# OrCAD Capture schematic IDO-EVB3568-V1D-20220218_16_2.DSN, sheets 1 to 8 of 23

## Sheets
1 P01. Revision History: title: IDO-EVB3568-V1; note: Revision History
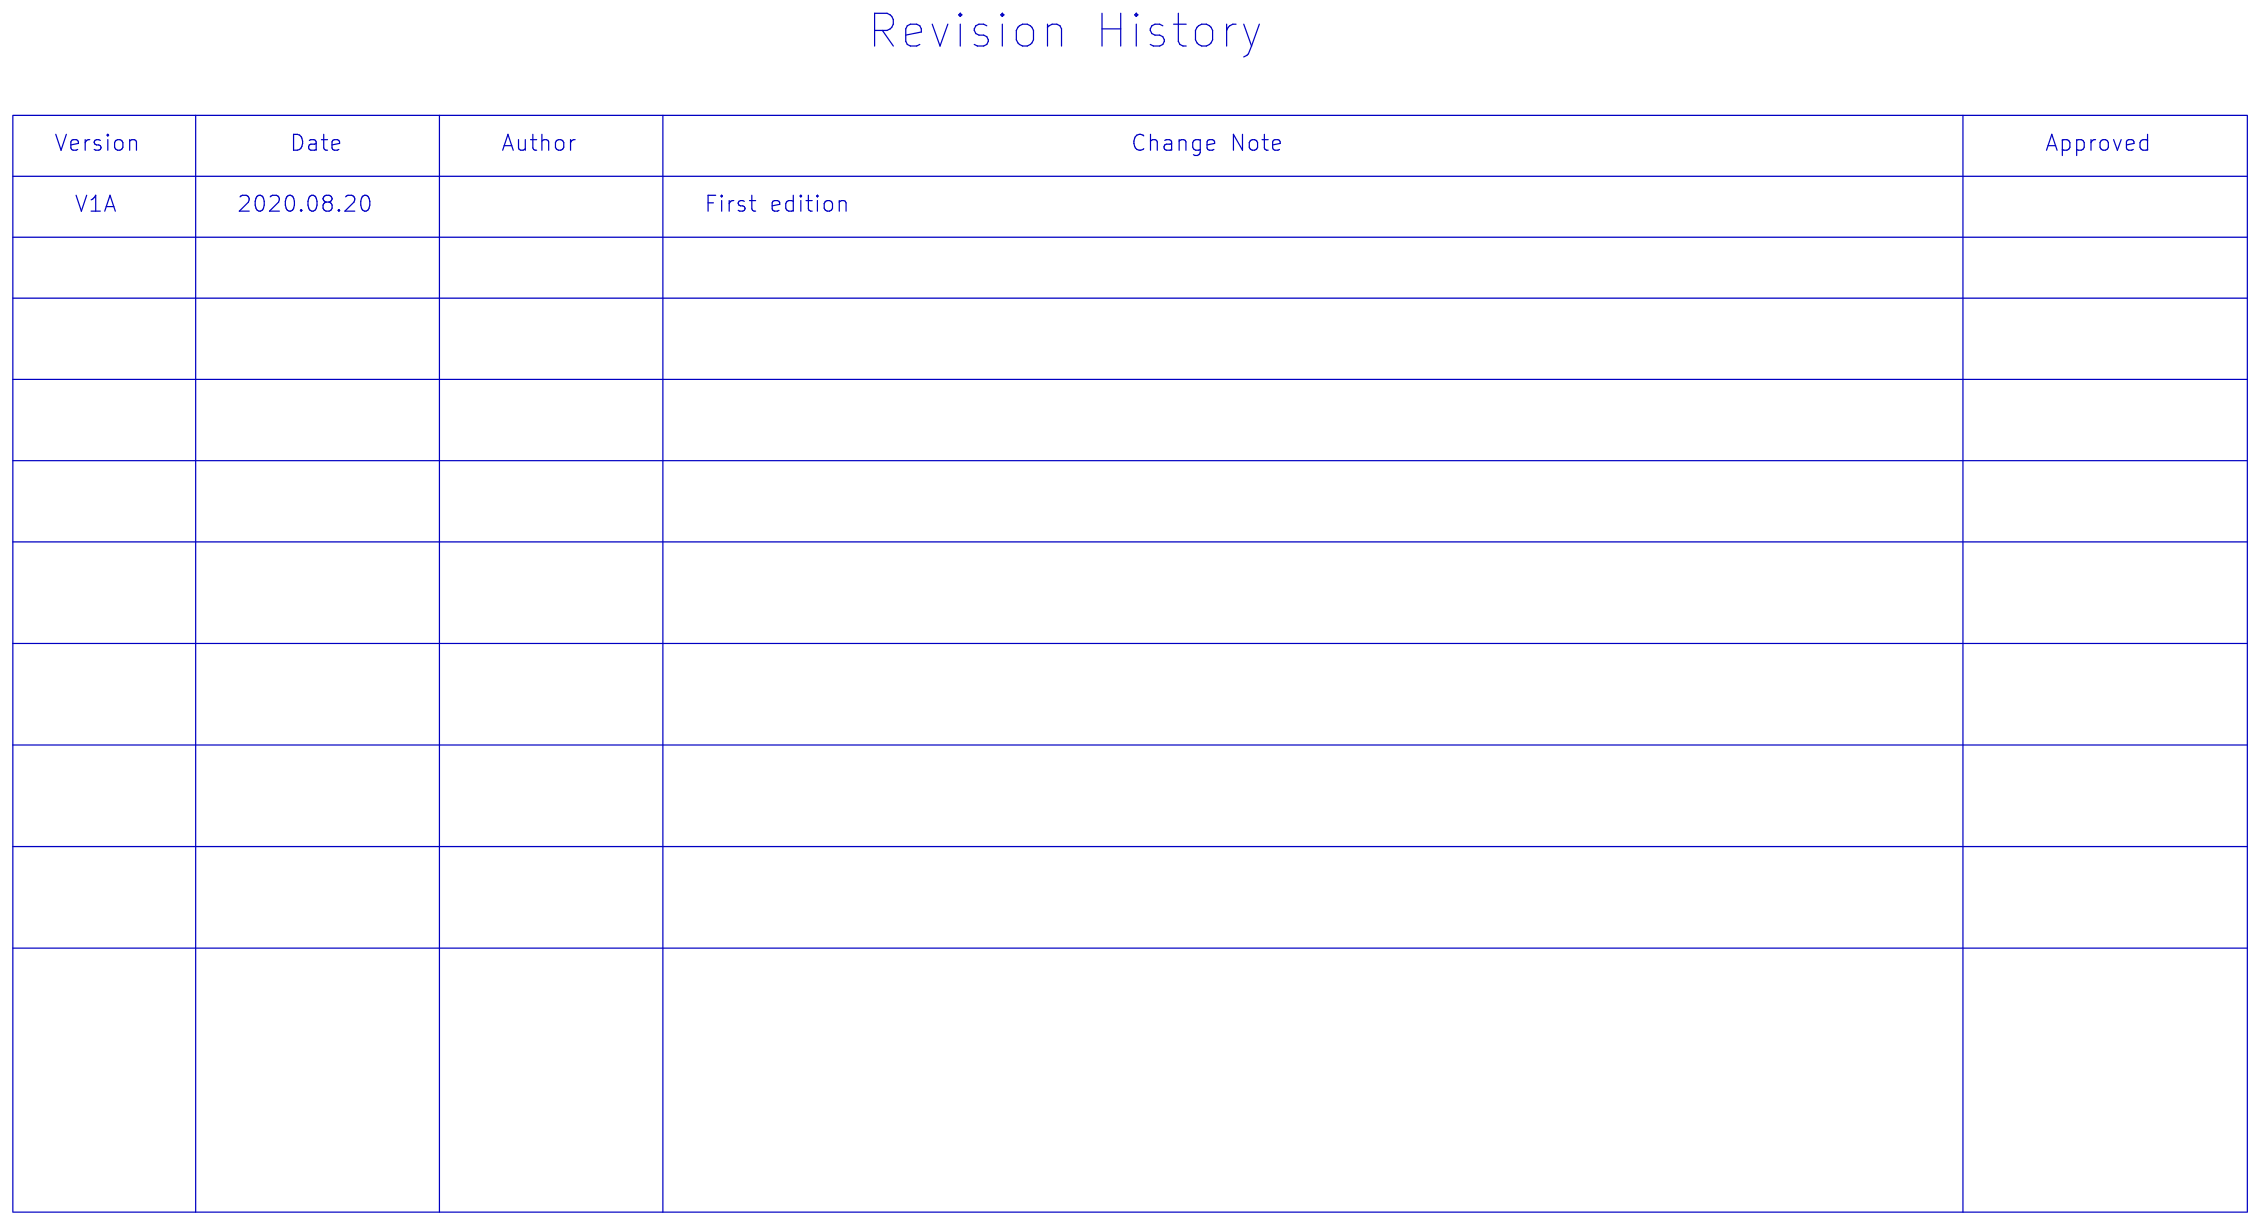
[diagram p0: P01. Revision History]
2 P02. Block Diagram: note: Block Diagram
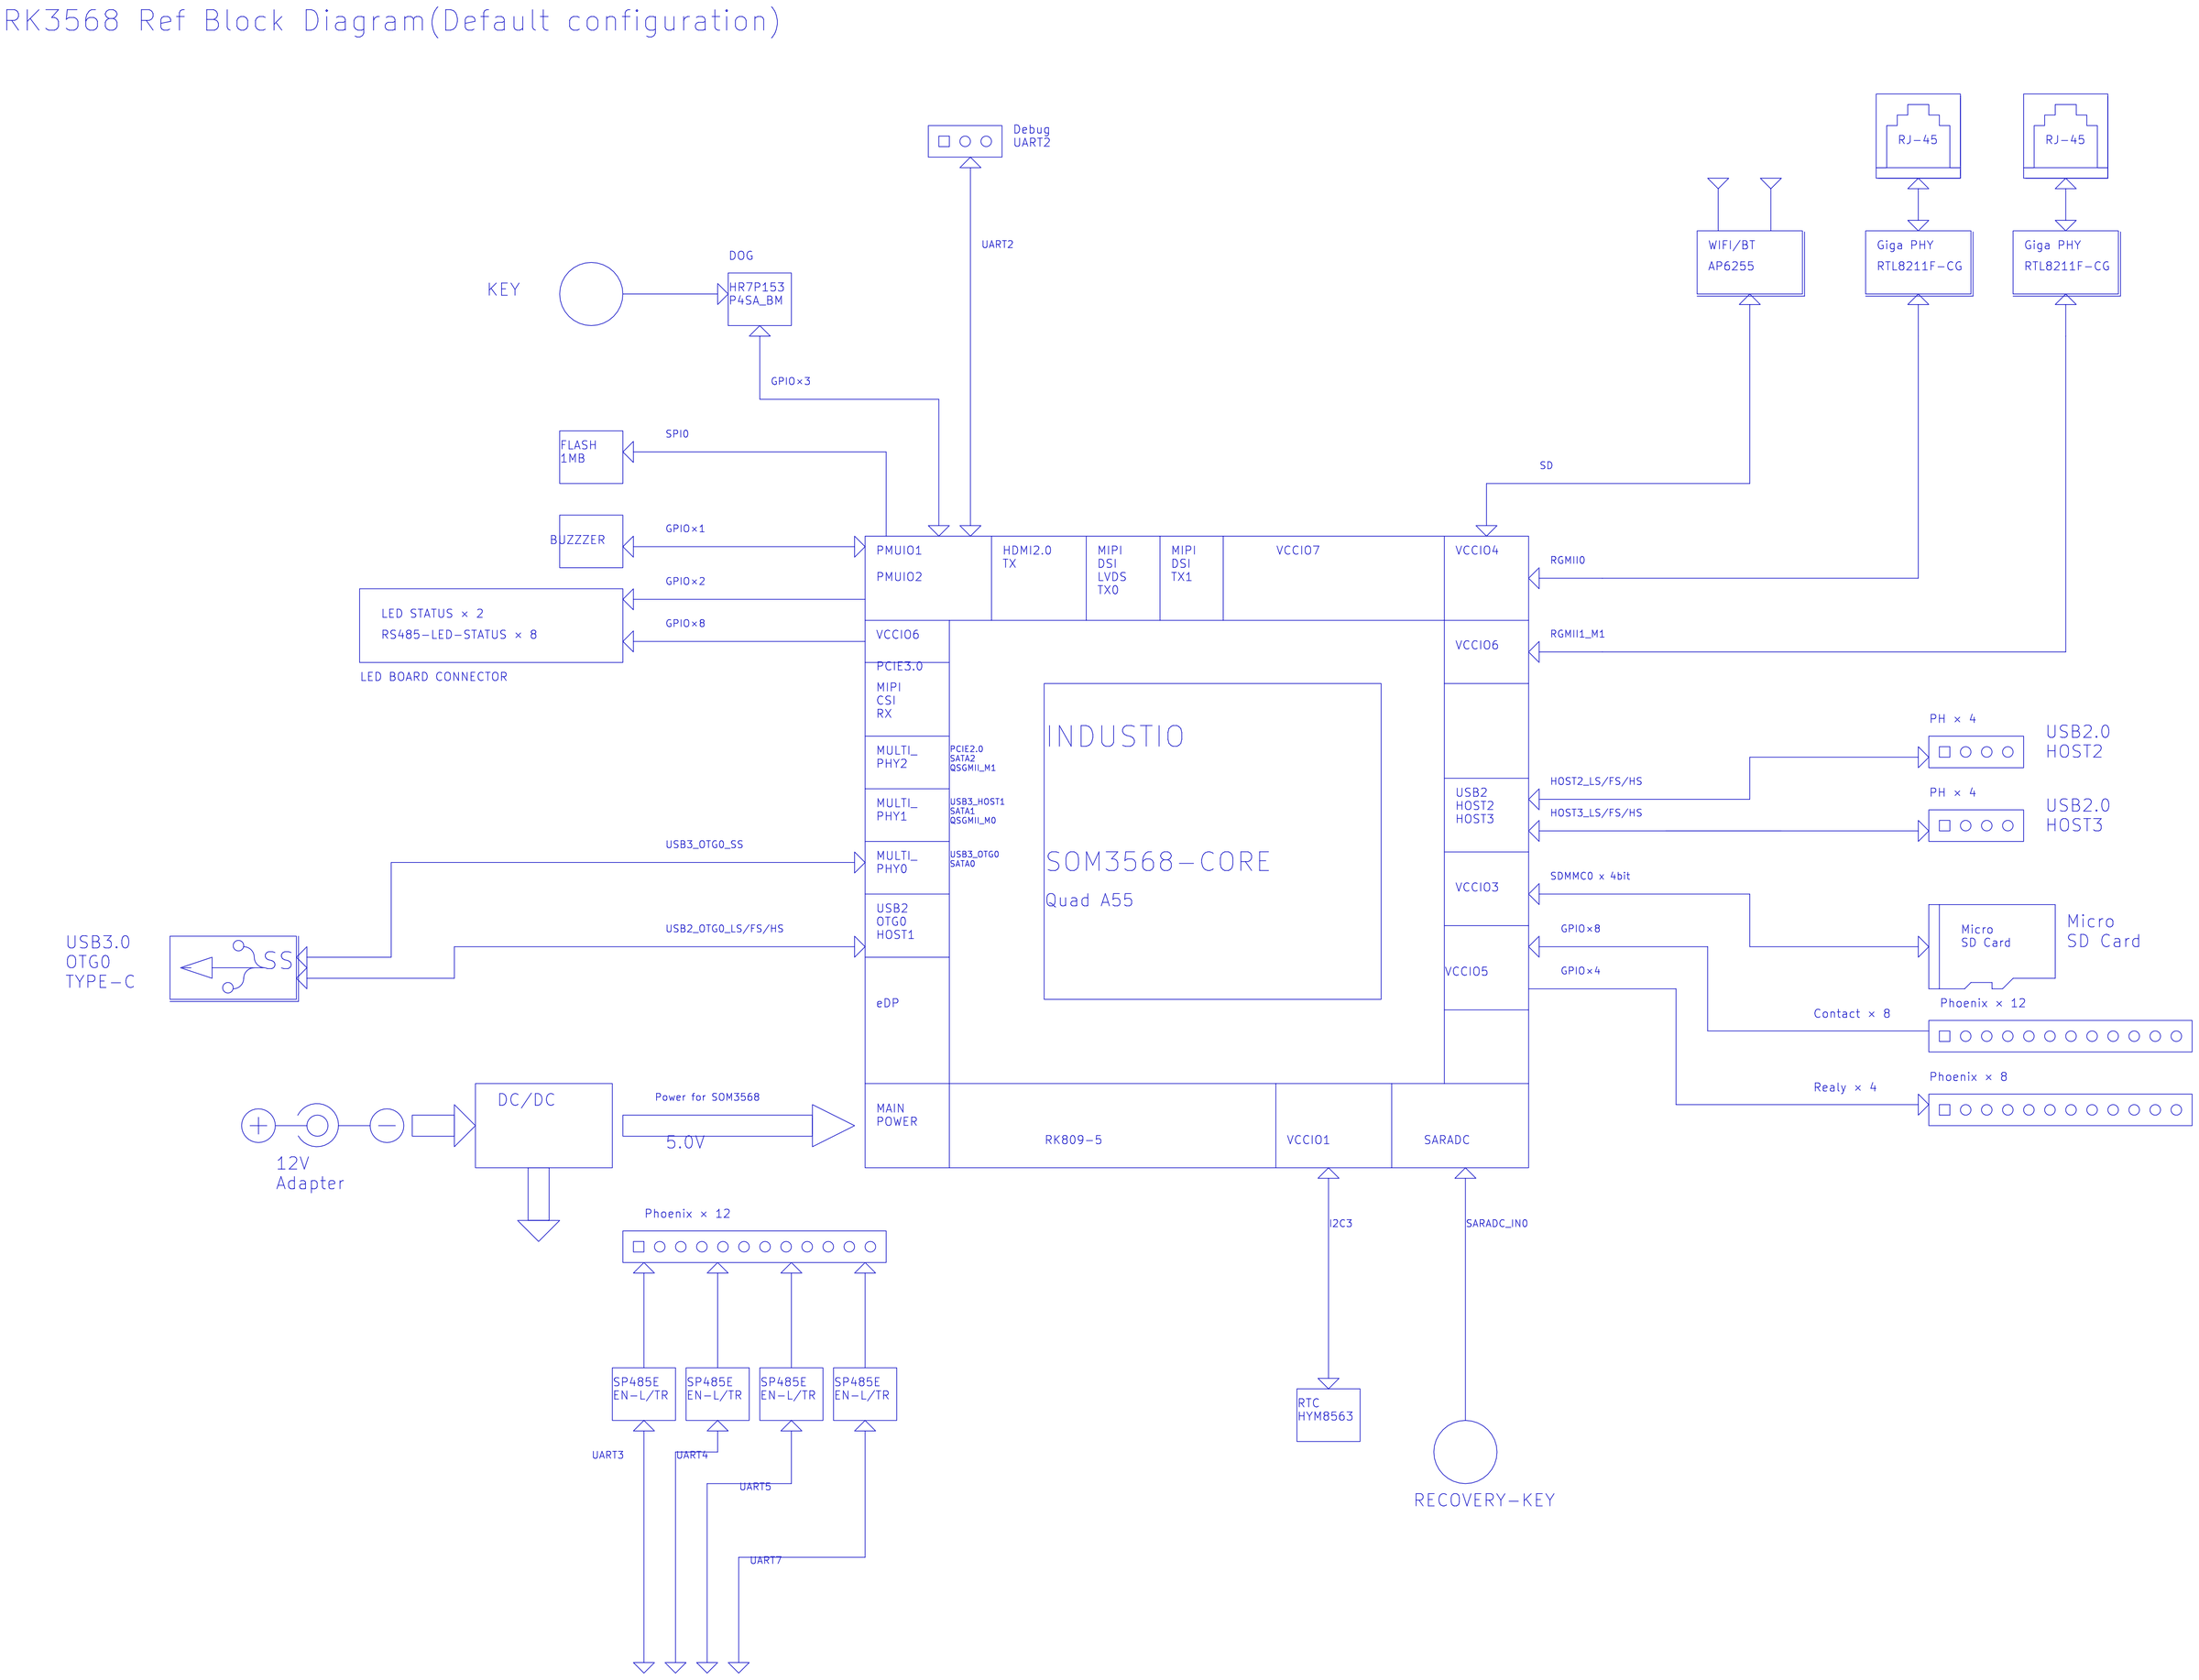
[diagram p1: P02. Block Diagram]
3 P03. Power Diagram: note: Power Diagram
4 P04. Power_DC IN: size A3; note: Power_DC IN
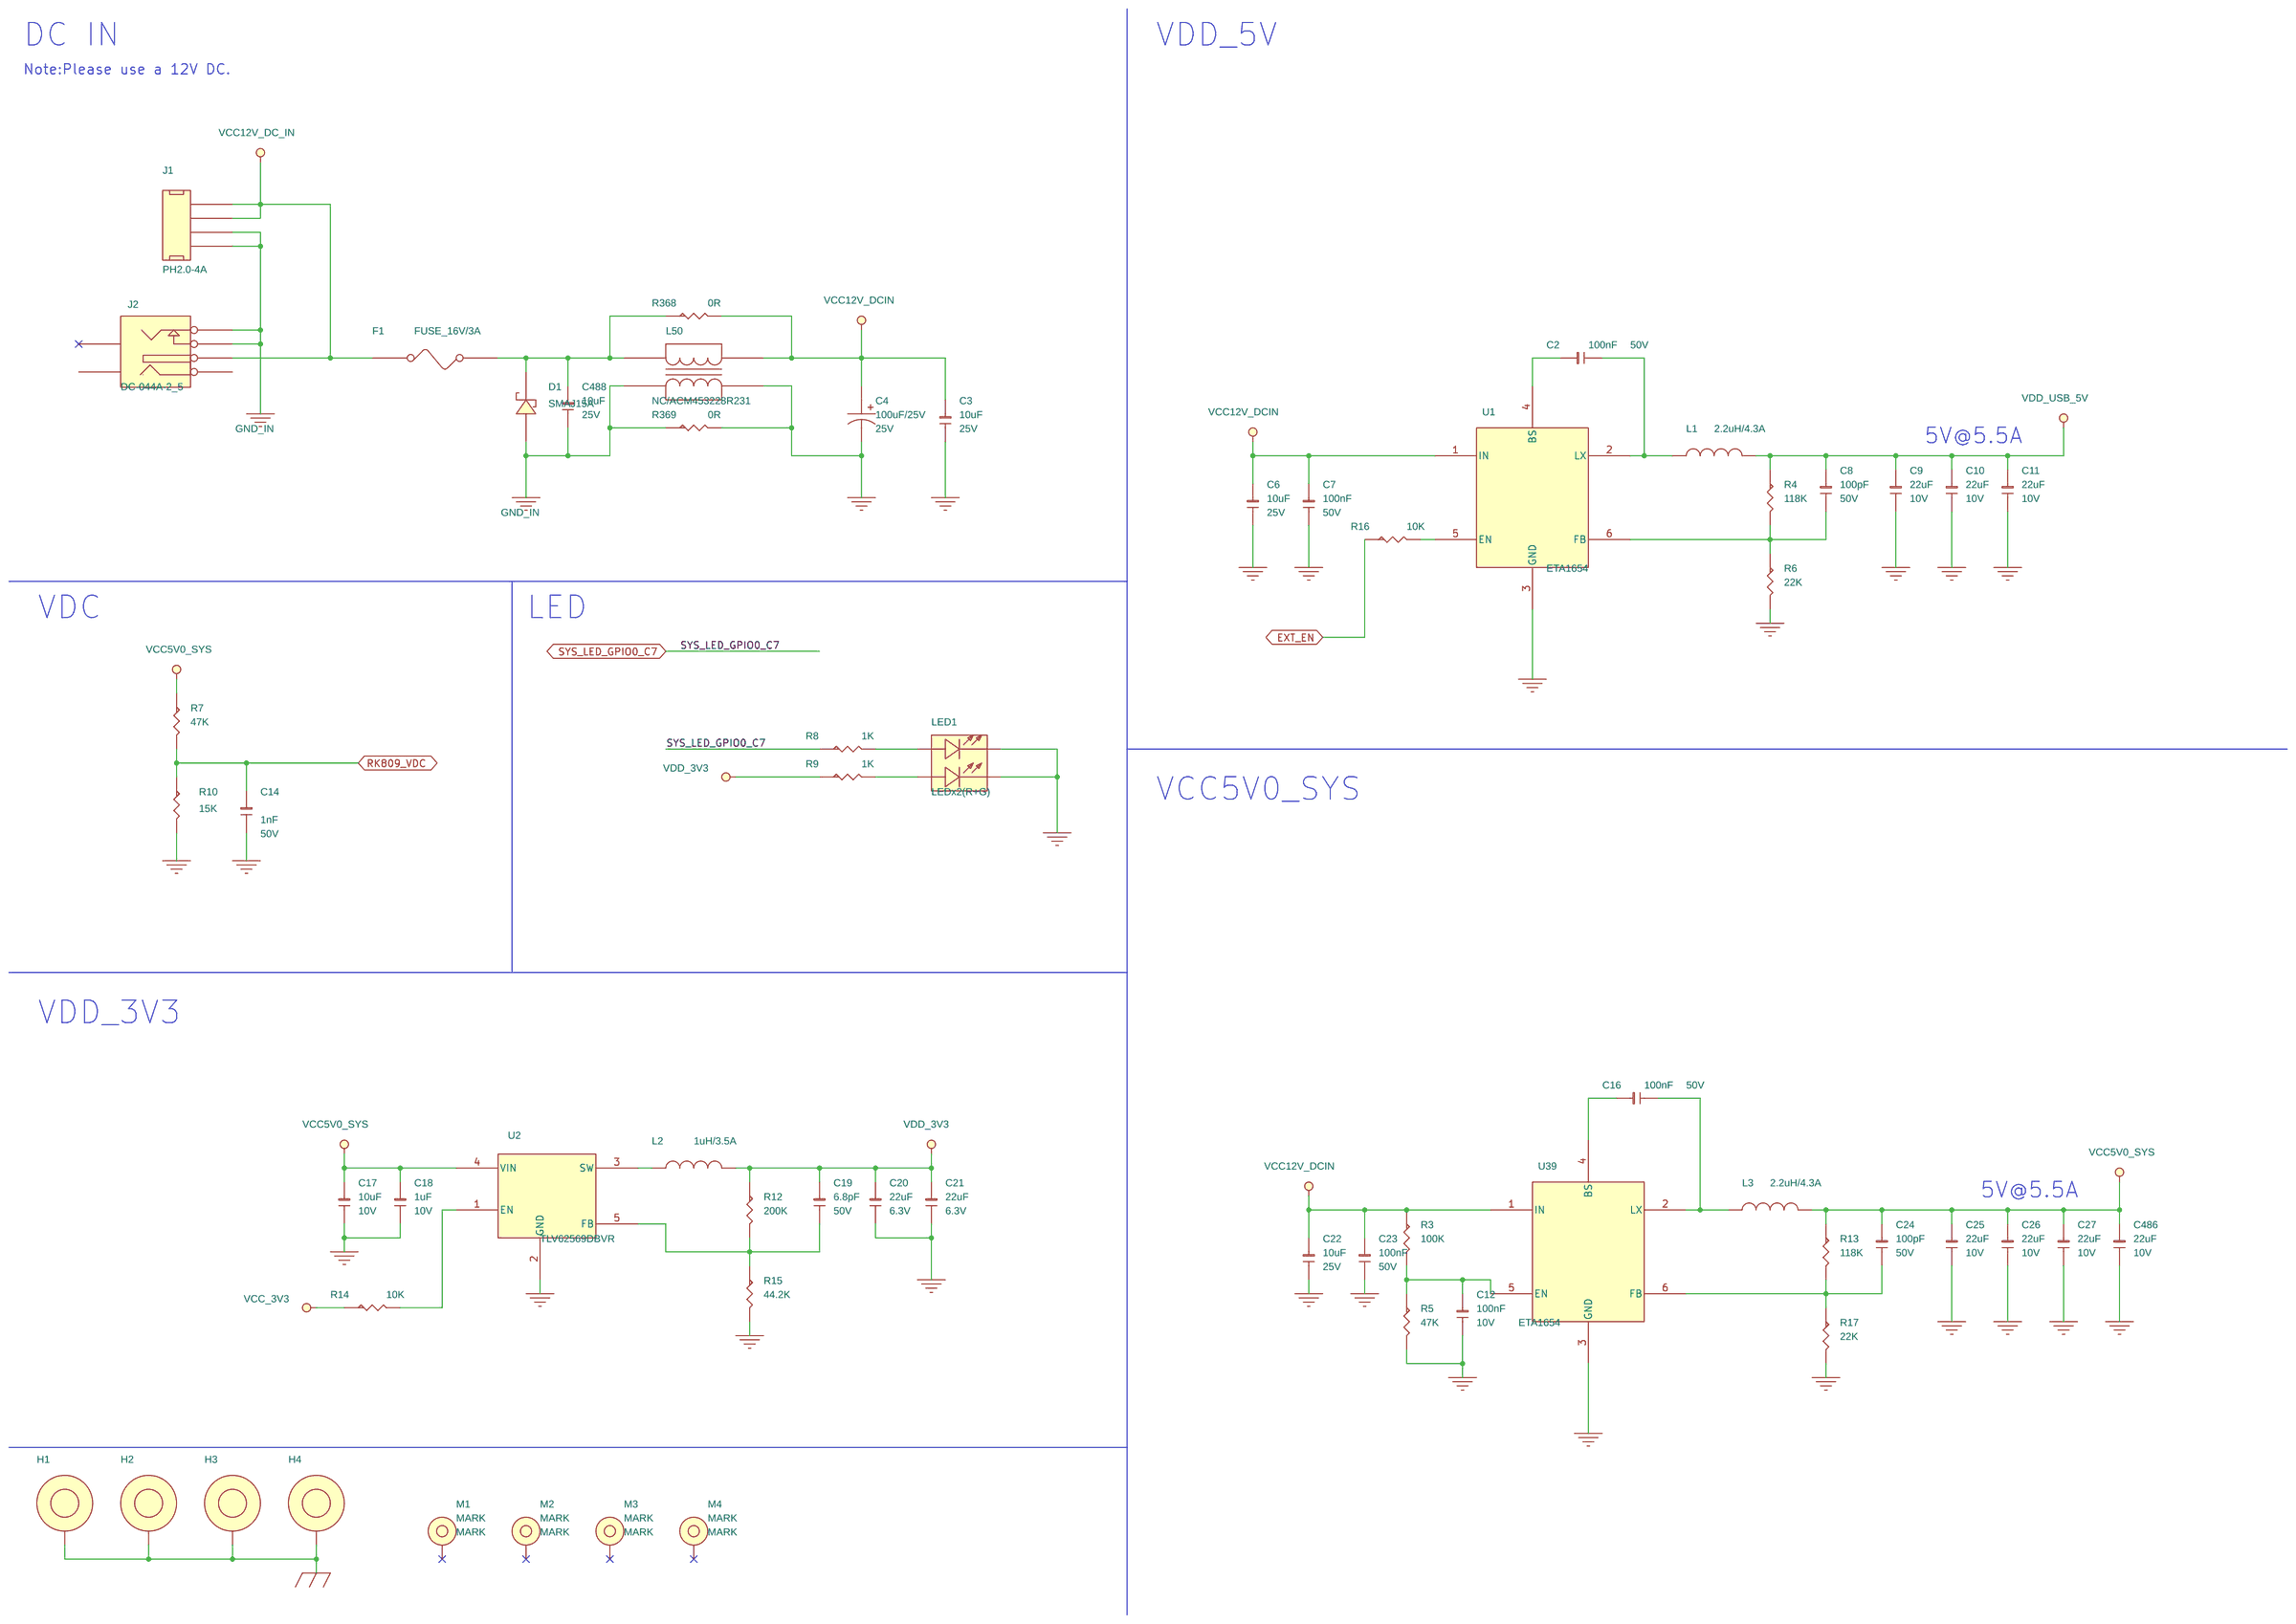
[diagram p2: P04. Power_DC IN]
5 P05. SOM3568-RK3568-Core: size A1; note: SOM3568-RK3568-Core
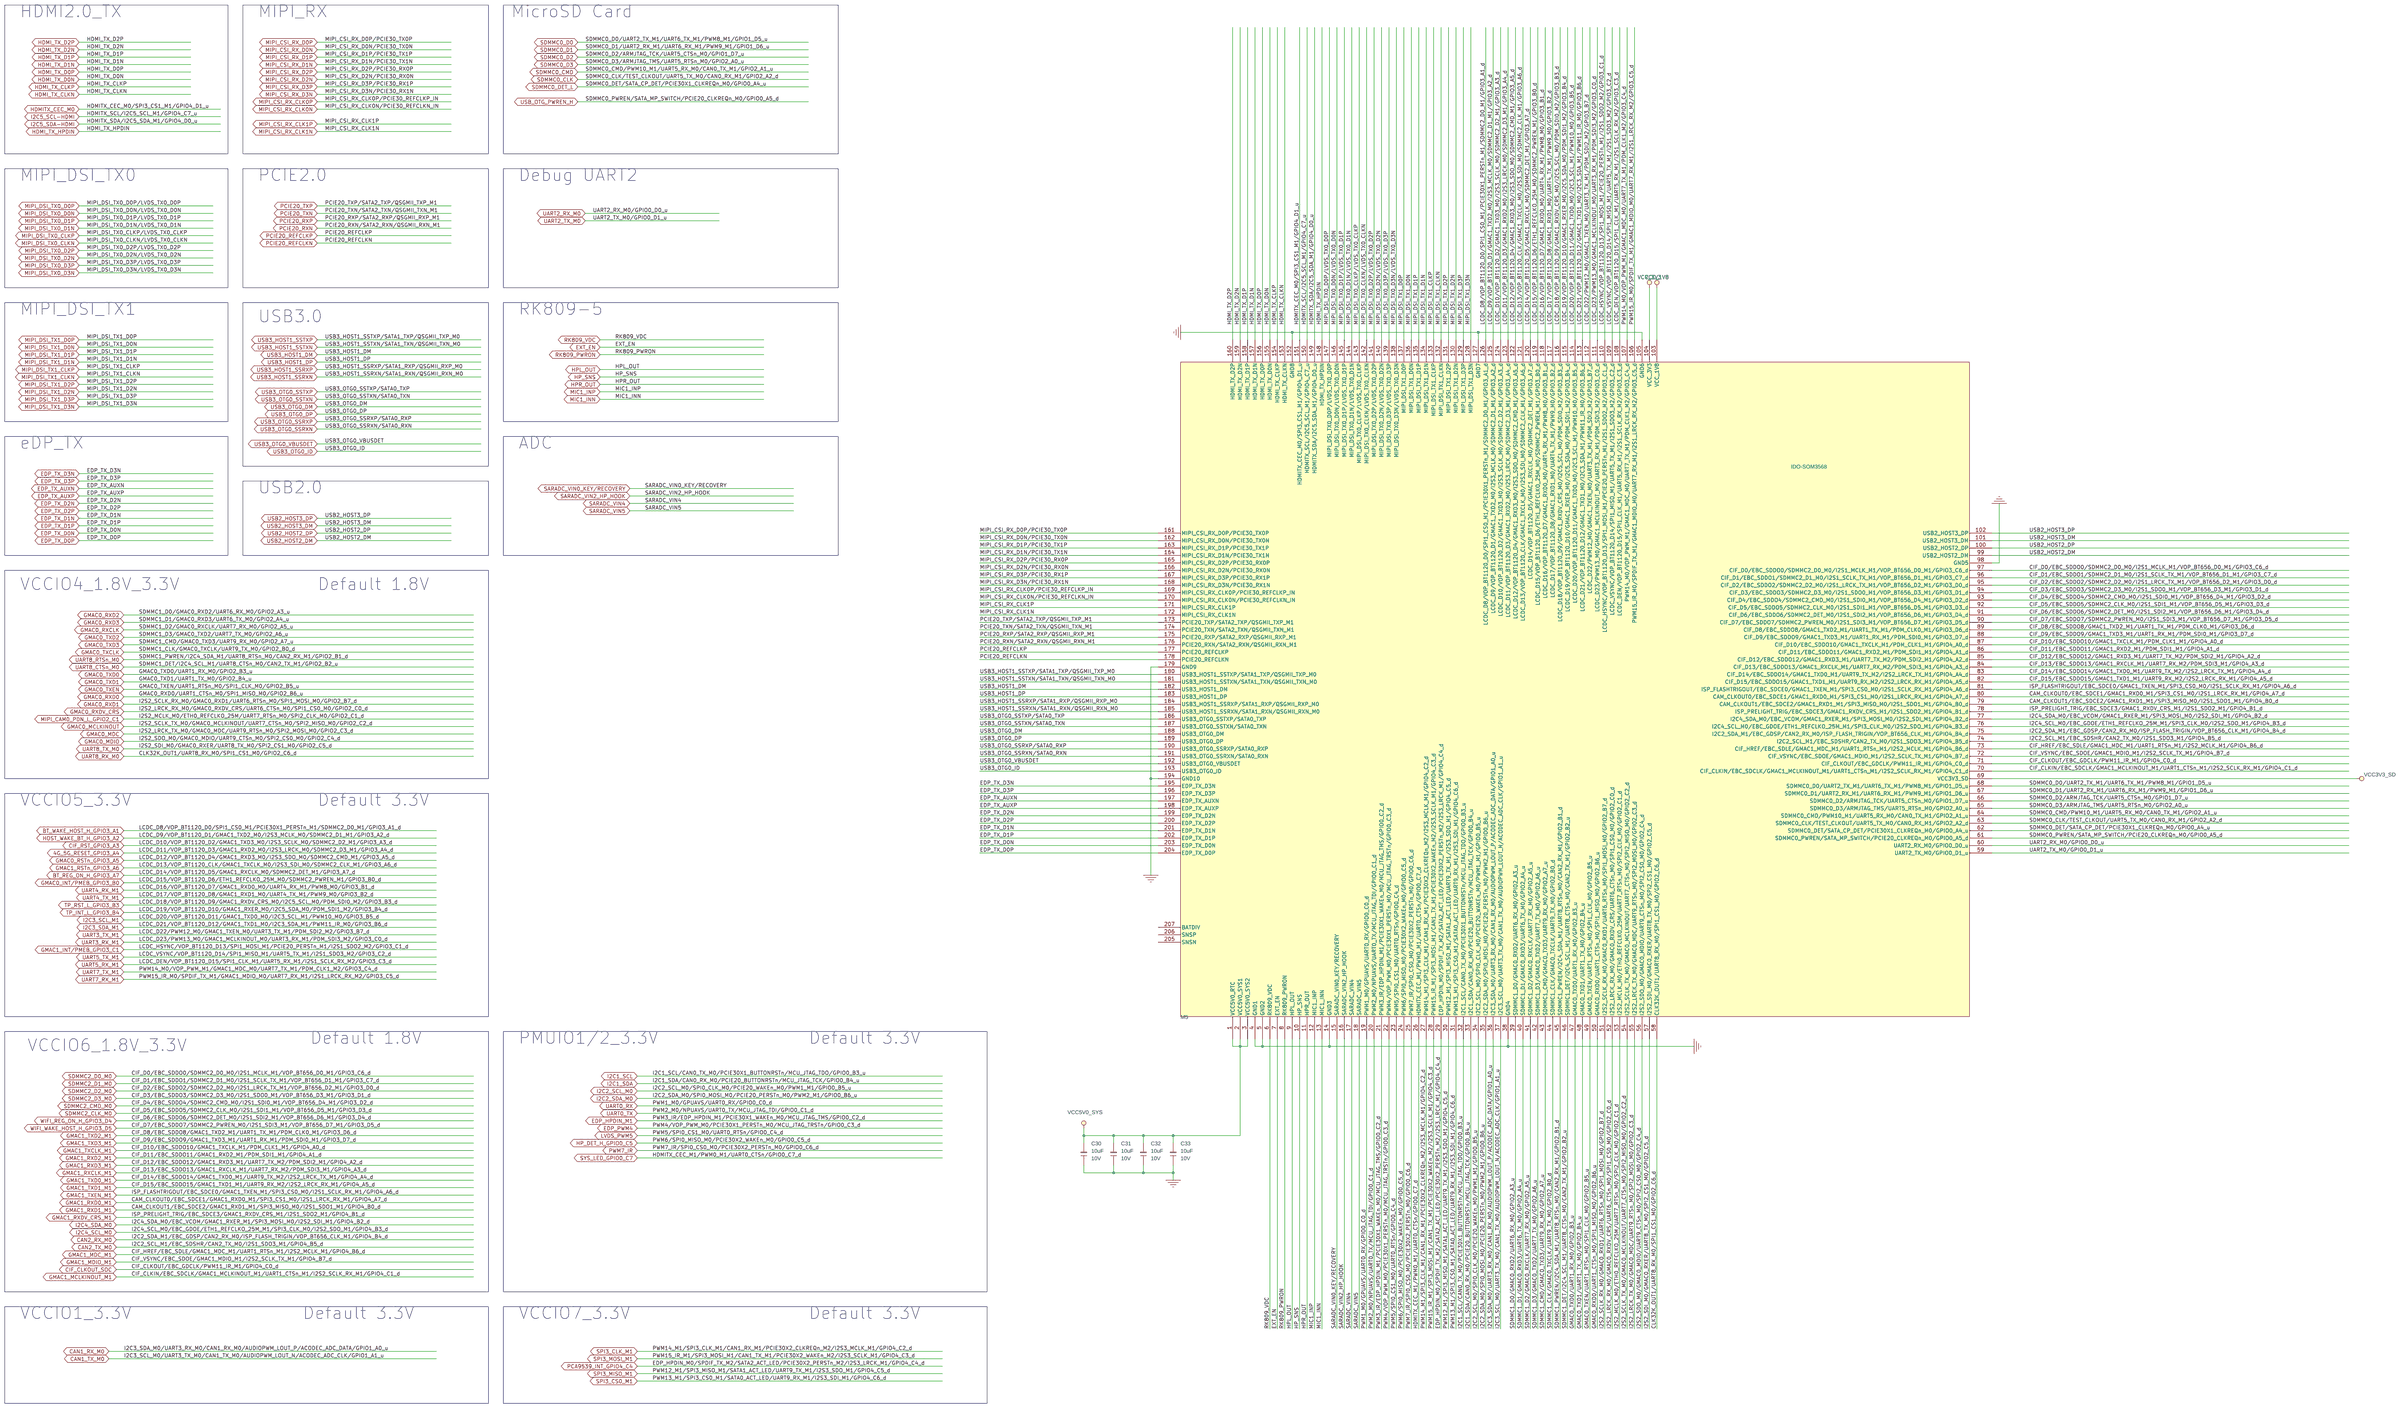
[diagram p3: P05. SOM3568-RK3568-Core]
6 P06. Flash-MicroSD Card: size A4; note: Flash-MicroSD Card
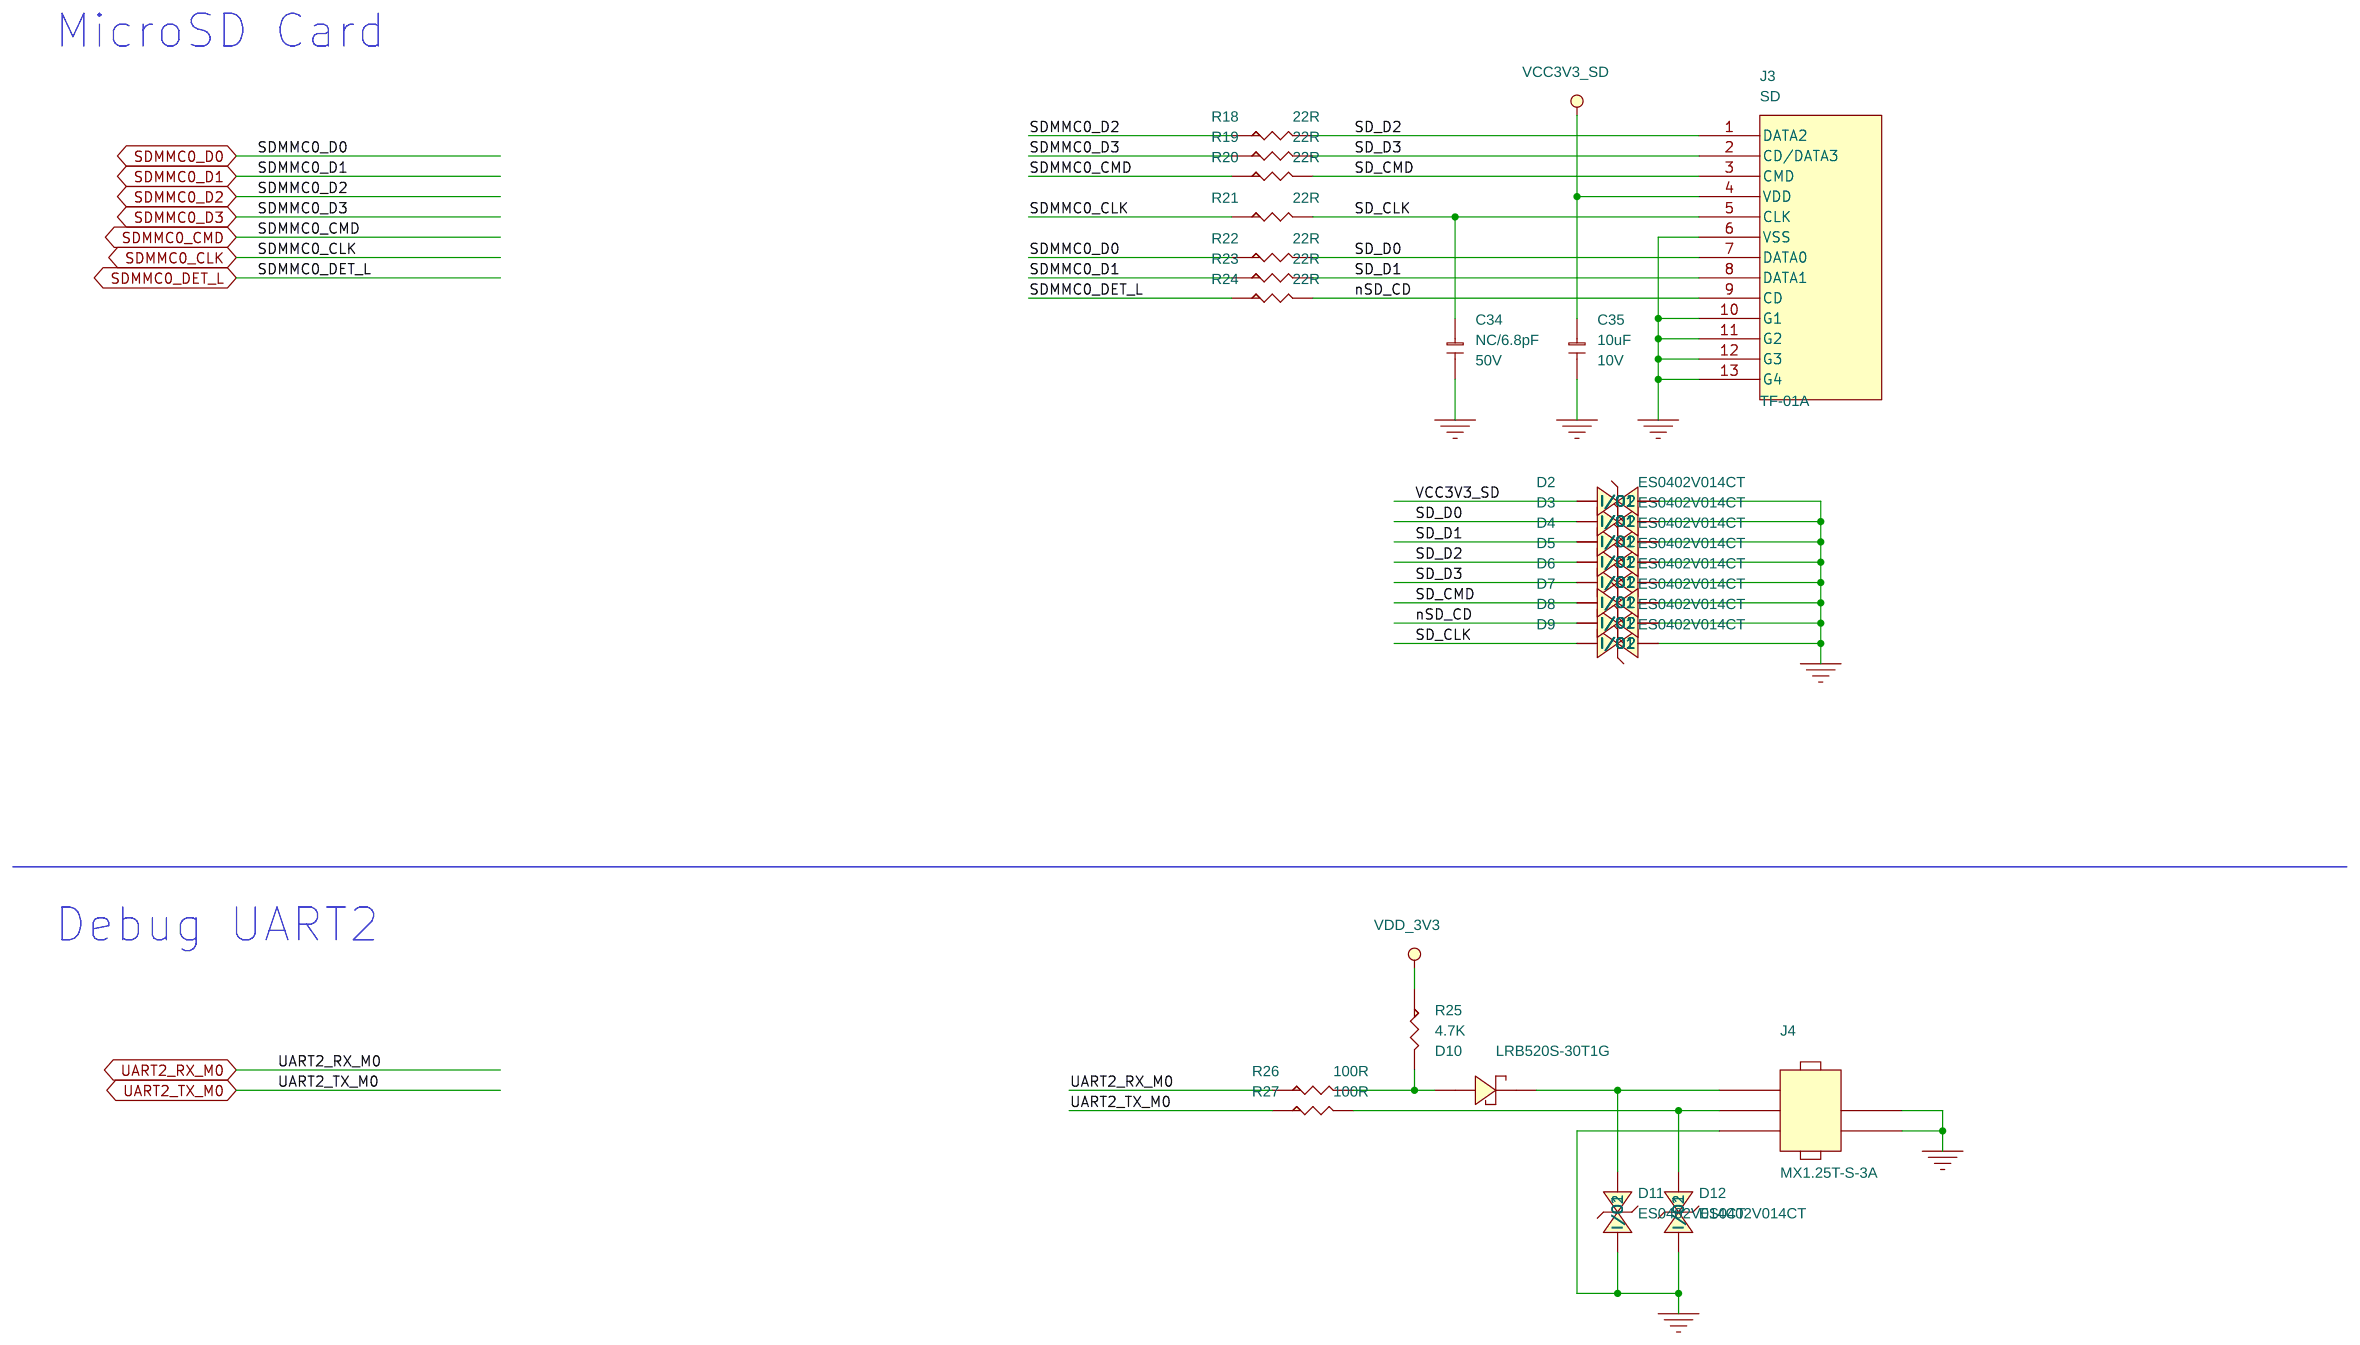
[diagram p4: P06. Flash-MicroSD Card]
7 P08. HUB-FE2.1: size A2; note: HUB-FE2.1
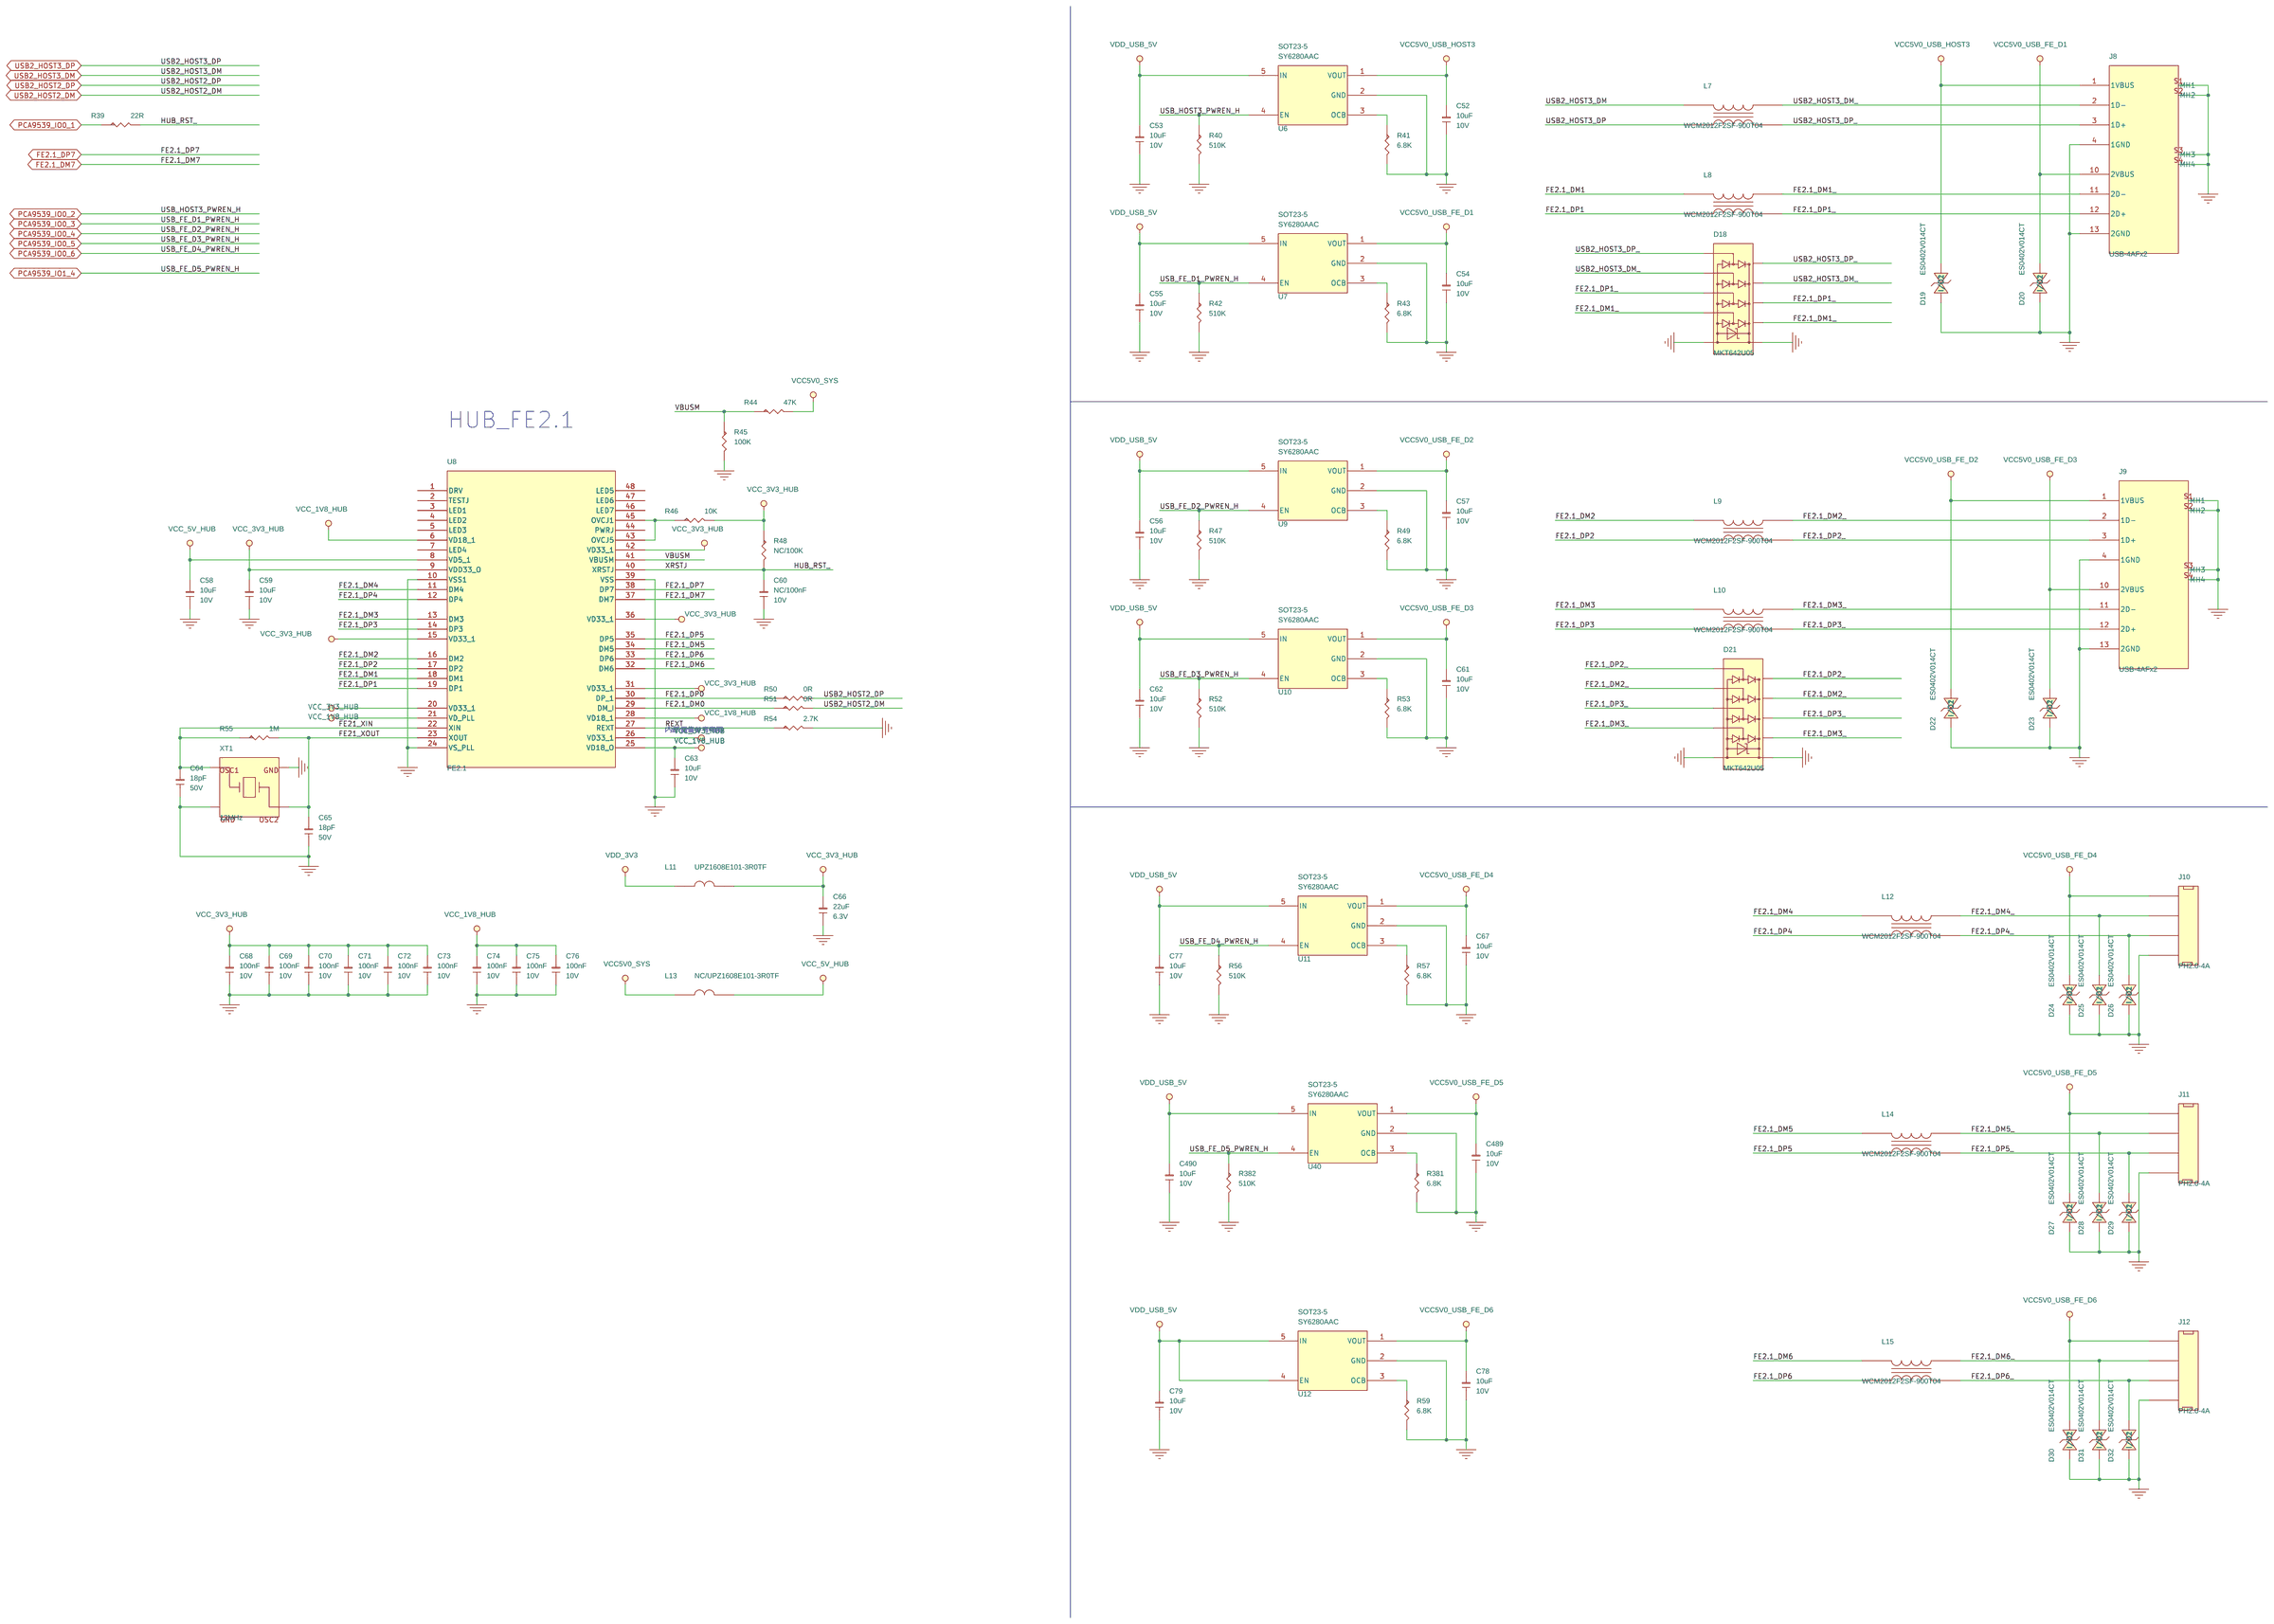
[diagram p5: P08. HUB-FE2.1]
8 P10. Audio-Headphone+SingleMic: size A3; note: Audio-Headphone+SingleMic
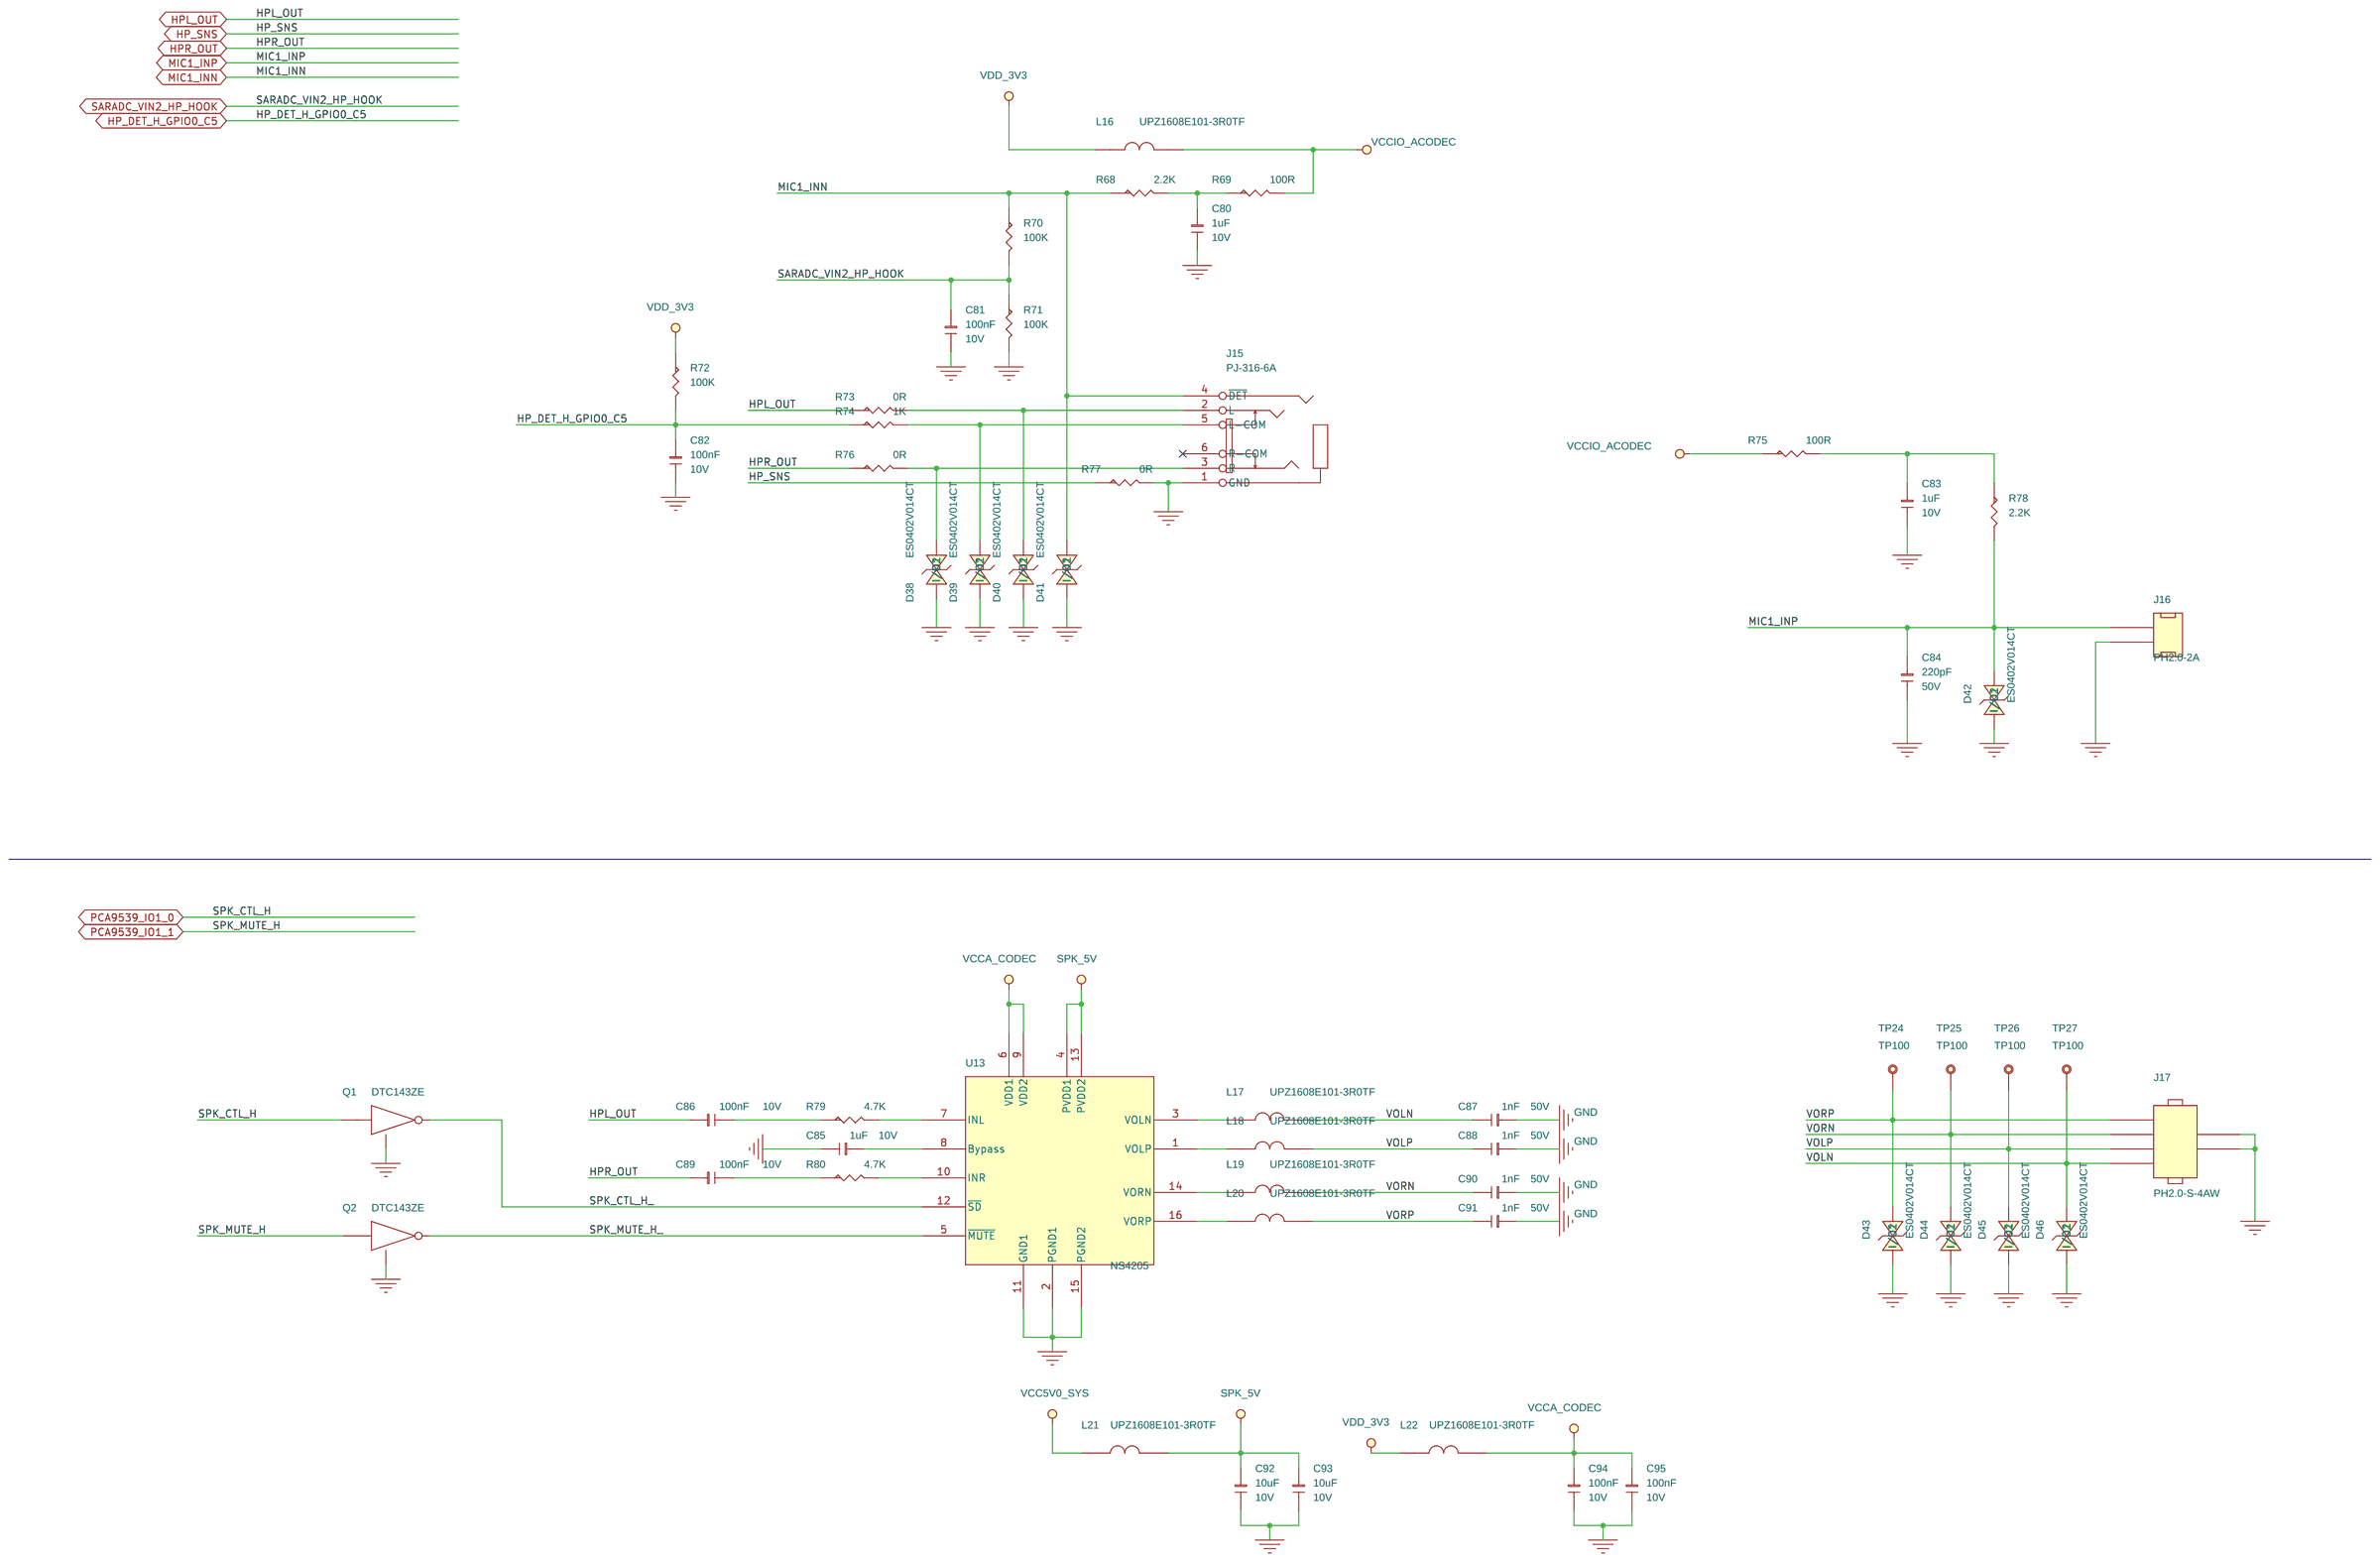
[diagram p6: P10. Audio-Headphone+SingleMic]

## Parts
sheet P04. Power_DC IN
C2  100nF  [C0402L]
C3  10uF  [C0805L]
C4  100uF/25V  [CAPAE660X770]
C6  10uF  [C0805L]
C7  100nF  [C0402L]
C8  100pF  [C0402L]
C9  22uF  [C0805L]
C10  22uF  [C0805L]
C11  22uF  [C0805L]
C12  100nF  [C0402L]
C14  1nF  [C0402L]
C16  100nF  [C0402L]
C17  10uF  [C0603L]
C18  1uF  [C0402L]
C19  6.8pF  [C0402L]
C20  22uF  [C0603L]
C21  22uF  [C0603L]
C22  10uF  [C0805L]
C23  100nF  [C0402L]
C24  100pF  [C0402L]
C25  22uF  [C0805L]
C26  22uF  [C0805L]
C27  22uF  [C0805L]
C486  22uF  [C0805L]
C488  10uF  [C0805L]
D1  SMAJ15A  [SMA_DO-214AC]
F1  FUSE_16V/3A  [SMD1812]
H1  HOLE  [mtg300_500]
H2  HOLE  [mtg300_500]
H3  HOLE  [mtg300_500]
H4  HOLE  [mtg300_500]
J1  PH2.0-4A  [PH200-4A]
J2  DC-044A-2_5  [DC-044A-2_5]
L1  2.2uH/4.3A  [L4040]
L2  1uH/3.5A  [L2520]
L3  2.2uH/4.3A  [L4040]
L50  NC/ACM453228R231  [CMLP-ACM4532]
LED1  LEDx2(R+G)  [LED_P254_2X2DIP]
M1  MARK  [MARK]
M2  MARK  [MARK]
M3  MARK  [MARK]
M4  MARK  [MARK]
R3  100K  [R0402L]
R4  118K  [R0402L]
R5  47K  [R0402L]
R6  22K  [R0402L]
R7  47K  [R0402L]
R8  1K  [R0402L]
R9  1K  [R0402L]
R10  15K  [R0402L]
R12  200K  [R0402L]
R13  118K  [R0402L]
R14  10K  [R0402L]
R15  44.2K  [R0402L]
R16  10K  [R0402L]
R17  22K  [R0402L]
R368  0R  [R0805L]
R369  0R  [R0805L]
U1  ETA1654  [SOT563]
U2  TLV62569DBVR  [SOT23-5]
U39  ETA1654  [SOT563]
sheet P05. SOM3568-RK3568-Core
C30  10uF  [C0603L]
C31  10uF  [C0603L]
C32  10uF  [C0603L]
C33  10uF  [C0603L]
M5  IDO-SOM3568  [SOM3568-204P]
sheet P06. Flash-MicroSD Card
C34  NC/6.8pF  [C0402L]
C35  10uF  [C0603L]
D2  ES0402V014CT  [V0402]
D3  ES0402V014CT  [V0402]
D4  ES0402V014CT  [V0402]
D5  ES0402V014CT  [V0402]
D6  ES0402V014CT  [V0402]
D7  ES0402V014CT  [V0402]
D8  ES0402V014CT  [V0402]
D9  ES0402V014CT  [V0402]
D10  LRB520S-30T1G  [SOD523]
D11  ES0402V014CT  [V0402]
D12  ES0402V014CT  [V0402]
J3  SD  [TF-01A]
J4  MX1.25T-S-3A  [MX125T-S-3A]
R18  22R  [R0402L]
R19  22R  [R0402L]
R20  22R  [R0402L]
R21  22R  [R0402L]
R22  22R  [R0402L]
R23  22R  [R0402L]
R24  22R  [R0402L]
R25  4.7K  [R0402L]
R26  100R  [R0402L]
R27  100R  [R0402L]
sheet P08. HUB-FE2.1
C52  10uF  [C0603L]
C53  10uF  [C0603L]
C54  10uF  [C0603L]
C55  10uF  [C0603L]
C56  10uF  [C0603L]
C57  10uF  [C0603L]
C58  10uF  [C0603L]
C59  10uF  [C0603L]
C60  NC/100nF  [C0402L]
C61  10uF  [C0603L]
C62  10uF  [C0603L]
C63  10uF  [C0603L]
C64  18pF  [C0402L]
C65  18pF  [C0402L]
C66  22uF  [C0603L]
C67  10uF  [C0603L]
C68  100nF  [C0402L]
C69  100nF  [C0402L]
C70  100nF  [C0402L]
C71  100nF  [C0402L]
C72  100nF  [C0402L]
C73  100nF  [C0402L]
C74  100nF  [C0402L]
C75  100nF  [C0402L]
C76  100nF  [C0402L]
C77  10uF  [C0603L]
C78  10uF  [C0603L]
C79  10uF  [C0603L]
C489  10uF  [C0603L]
C490  10uF  [C0603L]
D18  MKT642U05  [ESD-DFN2510A-10]
D19  ES0402V014CT  [V0402]
D20  ES0402V014CT  [V0402]
D21  MKT642U05  [ESD-DFN2510A-10]
D22  ES0402V014CT  [V0402]
D23  ES0402V014CT  [V0402]
D24  ES0402V014CT  [V0402]
D25  ES0402V014CT  [V0402]
D26  ES0402V014CT  [V0402]
D27  ES0402V014CT  [V0402]
D28  ES0402V014CT  [V0402]
D29  ES0402V014CT  [V0402]
D30  ES0402V014CT  [V0402]
D31  ES0402V014CT  [V0402]
D32  ES0402V014CT  [V0402]
J8  USB-4AFx2  [dural_usb_af_2x]
J9  USB-4AFx2  [dural_usb_af_2x]
J10  PH2.0-4A  [PH200-4A]
J11  PH2.0-4A  [PH200-4A]
J12  PH2.0-4A  [PH200-4A]
L7  WCM2012F2SF-900T04  [CMLS-ACM2012]
L8  WCM2012F2SF-900T04  [CMLS-ACM2012]
L9  WCM2012F2SF-900T04  [CMLS-ACM2012]
L10  WCM2012F2SF-900T04  [CMLS-ACM2012]
L11  UPZ1608E101-3R0TF  [L0603]
L12  WCM2012F2SF-900T04  [CMLS-ACM2012]
L13  NC/UPZ1608E101-3R0TF  [L0603]
L14  WCM2012F2SF-900T04  [CMLS-ACM2012]
L15  WCM2012F2SF-900T04  [CMLS-ACM2012]
R39  22R  [R0402L]
R40  510K  [R0402L]
R41  6.8K  [R0402L]
R42  510K  [R0402L]
R43  6.8K  [R0402L]
R44  47K  [R0402L]
R45  100K  [R0402L]
R46  10K  [R0402L]
R47  510K  [R0402L]
R48  NC/100K  [R0402L]
R49  6.8K  [R0402L]
R50  0R  [R0402L]
R51  0R  [R0402L]
R52  510K  [R0402L]
R53  6.8K  [R0402L]
R54  2.7K  [R0402L]
R55  1M  [R0402L]
R56  510K  [R0402L]
R57  6.8K  [R0402L]
R59  6.8K  [R0402L]
R381  6.8K  [R0402L]
R382  510K  [R0402L]
U6  SY6280AAC  [SOT23-5]
U7  SY6280AAC  [SOT23-5]
U8  FE2.1  [FE2_1-LQFP48]
U9  SY6280AAC  [SOT23-5]
U10  SY6280AAC  [SOT23-5]
U11  SY6280AAC  [SOT23-5]
U12  SY6280AAC  [SOT23-5]
U40  SY6280AAC  [SOT23-5]
XT1  12MHz  [xtal_32x25_4p]
sheet P10. Audio-Headphone+SingleMic
C80  1uF  [C0402L]
C81  100nF  [C0402L]
C82  100nF  [C0402L]
C83  1uF  [C0402L]
C84  220pF  [C0402L]
C85  1uF  [C0402L]
C86  100nF  [C0402L]
C87  1nF  [C0402L]
C88  1nF  [C0402L]
C89  100nF  [C0402L]
C90  1nF  [C0402L]
C91  1nF  [C0402L]
C92  10uF  [C0603L]
C93  10uF  [C0603L]
C94  100nF  [C0402L]
C95  100nF  [C0402L]
D38  ES0402V014CT  [V0402]
D39  ES0402V014CT  [V0402]
D40  ES0402V014CT  [V0402]
D41  ES0402V014CT  [V0402]
D42  ES0402V014CT  [V0402]
D43  ES0402V014CT  [V0402]
D44  ES0402V014CT  [V0402]
D45  ES0402V014CT  [V0402]
D46  ES0402V014CT  [V0402]
J15  PJ-316-6A  [PJ-316A-6A]
J16  PH2.0-2A  [PH200-2A]
J17  PH2.0-S-4AW  [PH200-S-4AWZ]
L16  UPZ1608E101-3R0TF  [L0603]
L17  UPZ1608E101-3R0TF  [L0603]
L18  UPZ1608E101-3R0TF  [L0603]
L19  UPZ1608E101-3R0TF  [L0603]
L20  UPZ1608E101-3R0TF  [L0603]
L21  UPZ1608E101-3R0TF  [L0603]
L22  UPZ1608E101-3R0TF  [L0603]
Q1  DTC143ZE  [SOT523]
Q2  DTC143ZE  [SOT523]
R68  2.2K  [R0402L]
R69  100R  [R0402L]
R70  100K  [R0402L]
R71  100K  [R0402L]
R72  100K  [R0402L]
R73  0R  [R0402L]
R74  1K  [R0402L]
R75  100R  [R0402L]
R76  0R  [R0402L]
R77  0R  [R0402L]
R78  2.2K  [R0402L]
R79  4.7K  [R0402L]
R80  4.7K  [R0402L]
TP24  TP100  [TP100]
TP25  TP100  [TP100]
TP26  TP100  [TP100]
TP27  TP100  [TP100]
U13  NS4205  [NS4205-SOP16]

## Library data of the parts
C2 C7 C16 C23 = C-0402: DSC1: ±10%; DSC2: 50V; DSC3: X7R; ERP Number: 1010200128; ID: 61; Manufacture: 三星|国巨|村田; Part Name: 贴片电容; Part Number: C020102120061; Price: 0.05
C3 C6 C22 C488 = C-0805: DSC1: ±10%; DSC2: 25V; DSC3: X5R; ERP Number: 1010200144; ID: 74; Manufacture: 三星|国巨|村田; Part Name: 贴片电容; Part Number: C020102120074; Price: 0.09
C4 = C-AL-SMD: DSC1: ±20%; DSC2: 25V; DSC3: 低阻抗; DSC4: 2000H; DSC5: -55~105 ℃; DSC6: SMD,6.3x7.7mm; DSC7: LZ1E101M-CRE77(ST); ERP Number: 1010200266; ID: 6; Manufacture: 先科|立隆|三莹; Part Name: 贴片铝电容; Part Number: C020302140006; Price: 0.20
C8 C24 = C-0402: DSC1: ±5%; DSC2: 50V; DSC3: C0G; ERP Number: 1010200152; Manufacture: 三星|国巨|村田; Part Name: 贴片电容; Part Number: C020102120040; Price: 0.01
C9-C11 C25-C27 C486 = C-0805: DSC1: ±20%; DSC2: 10V; DSC3: X5R; ID: 75; Manufacture: 三星|国巨|村田; Part Name: 贴片电容; Part Number: C020102120075; Price: 0.11
C12 C60 C68-C76 C81 C82 C86 C89 C94 C95 = C-0402: DSC1: ±10%; DSC2: 10V; DSC3: X7R; ID: 60; Manufacture: 三星|国巨|村田; Part Name: 贴片电容; Part Number: C020102120060; Price: 0.01
C14 C87 C88 C90 C91 = C-0402: DSC1: ±10%; DSC2: 50V; DSC3: X7R; ERP Number: 1010200084; ID: 54; Manufacture: 三星|国巨|村田; Part Name: 贴片电容; Part Number: C020102120054; Price: 0.01
C17 C30-C33 C35 C52-C59 C61-C63 C67 C77-C79 C92 C93 C489 C490 = C-0603: DSC1: ±20%; DSC2: 10V; DSC3: X5R; ERP Number: 1010200076; ID: 71; Manufacture: 三星|国巨|村田; Part Name: 贴片电容; Part Number: C020102120071; Price: 0.05
C18 C80 C83 C85 = C-0402: DSC1: ±10%; DSC2: 10V; DSC3: X5R; ERP Number: 1010200054; ID: 64; Manufacture: 三星|国巨|村田; Part Name: 贴片电容; Part Number: C020102120064; Price: 0.02
C19 C34 = C-0402: DSC1: ±0.25PF; DSC2: 50V; DSC3: C0G; ERP Number: 1010200056; ID: 18; Manufacture: 三星|国巨|村田; Part Name: 贴片电容; Part Number: C020102120018; Price: 0.01
C20 C21 C66 = C-0603: DSC1: ±20%; DSC2: 6.3V; DSC3: X5R; ERP Number: 1010200133; ID: 72; Manufacture: 三星|国巨|村田; Part Name: 贴片电容; Part Number: C020102120072; Price: 0.06
D1 = DI-XI-S: DSC1: 单向; DSC2: Vrwm=15V; DSC3: VBR=16.7V; DSC4: Vc=24.4V; DSC5: Ipp=16.4A; DSC6: Ppp=400W; ERP Number: 1010800027; ID: 3; Manufacture: MDD|伯恩半导体; Part Name: TVS; Part Number: C040602260003
F1 = FUSE-SMD1812: DSC1: 16V; DSC2: 3A; DSC3: SMD1812P300TF/16V; ID: 8; Manufacture: RUILON; Part Name: 自恢复保险丝; Part Number: C160102670008; Price: 0.46
H1-H4 = HOLE
J1 = J-H-4P: DSC1: 4p; DSC2: 2.0mm间距; DSC3: 通孔180度直针; DSC4: 米黄色胶壳 耐高温; DSC5: A2001WV-4P(CJT); ID: 13; Part Name: PH; Part Number: J020302820003
J2 = J-DC-044A-2_5: DSC1: DC电源 内芯2.0mm 外径6mm 5脚插件 有定位柱; DSC2: 11.5*10.1*H7.3mm; DSC3: 插件; DSC4: DC-044A-2.5A-2.0(星坤); ID: 3; Part Name: DC座; Part Number: J100103010003
L1 L3 = L-IND: DSC1: ±20%; DSC2: Isat=6.1A; DSC3: Irms=4.3A; DSC4: 48mΩ; DSC5: 4.0*4.0*2.0mm; DSC6: WPN4020H2R2MT(顺络); ERP Number: 1010200404; ID: 20; Manufacture: 顺络; Part Name: 功率电感; Part Number: C060202340020; Price: 0.38
L2 = L-IND: DSC1: ±20%; DSC2: Isat=4.5A; DSC3: Irms=3.5A; DSC4: 37mΩ; DSC5: 2.5*2.0*1.2mm; DSC6: WPN252012E1R0MT(顺络); ID: 12; Manufacture: 顺络; Part Name: 功率电感; Part Number: C060202340012; Price: 0.22
L50 = L-CMLS-ACM2012-1: DSC2: 231Ω@100MHz; DSC3: 3.5A; DSC4: DCR=50mΩ; DSC5: -40℃ ~ +85℃; DSC6: SMD_4P,4.5x3.2x2.8mm; Manufacture: 驰兴; Part Name: 电源共模电感; Part Number: C060406183888; Price: 0.7
LED1 = D-LED-DIP-2: DSC1: 双孔座2位黑色方形灯柱 90度弯脚 左正右负 上红下绿; ID: 22; Part Name: LED; Part Number: C140202660018
M1-M4 = MARK: MARK Symble; Created by: JJJ; Priority: A; RK PN: MARK01
R3 R45 R48 R70-R72 = R-0402: DSC1: ±1%; DSC2: 1/16W; ERP Number: 1010200137; ID: 976; Part Name: 贴片电阻; Part Number: C011002080976; Price: 0.01
R4 R13 = R-0402: DSC1: ±1%; DSC2: 1/16W; ERP Number: 1010200366; ID: 983; Part Name: 贴片电阻; Part Number: C011002080983; Price: 0.01
R5 R7 R44 = R-0402: DSC1: ±1%; DSC2: 1/16W; ERP Number: 1010200446; ID: 935; Part Name: 贴片电阻; Part Number: C011002080935; Price: 0.01
R6 R17 = R-0402: DSC1: ±1%; DSC2: 1/16W; ID: 893; Part Name: 贴片电阻; Part Number: C011002080893; Price: 0.01
R8 R9 R74 = R-0402: DSC1: ±1%; DSC2: 1/16W; ERP Number: 1010200113; ID: 742; Part Name: 贴片电阻; Part Number: C011002080742; Price: 0.01
R10 = R-0402: DSC1: ±1%; DSC2: 1/16W; ERP Number: 1010200458; ID: 875; Part Name: 贴片电阻; Part Number: C011002080875; Price: 0.01
R12 = R-0402: DSC1: ±1%; DSC2: 1/16W; ERP Number: 1010200139; ID: 1,009; Part Name: 贴片电阻; Part Number: C011002081009; Price: 0.01
R14 R16 R46 = R-0402: DSC1: ±1%; DSC2: 1/16W; ERP Number: 1010200140; ID: 856; Part Name: 贴片电阻; Part Number: C011002080856; Price: 0.01
R15 = R-0402: DSC1: ±1%; DSC2: 1/16W; ERP Number: 1010200256; ID: 931; Part Name: 贴片电阻; Part Number: C011002080931; Price: 0.01
R368 R369 = R-0805: DSC1: ±1%; DSC2: 1/8W; ERP Number: 1010200199; ID: 1,448; Part Name: 贴片电阻; Part Number: C011002081448; Price: 0.01
U1 U39 = U-SY8105ADC_0: DSC1: Vi=4.5-18V; DSC2: Vo=0.6-18V; DSC3: Io=5A; DSC4: Vfb=0.6V; DSC5: 0.96; DSC6: 500KHz; DSC7: 同步降压; Manufacture: 矽力杰; Part Name: DCDC; Part Number: C070202410017; Price: 1.1
U2 = U-TLV62569DBVR: DSC1: Vi=2.5-5.5V; DSC2: Vo=0.6-5.5V; DSC3: Io=2A; DSC4: Vfb=0.6V; DSC5: 0.95; DSC6: 1.5MHz; DSC7: 同步降压 轻载效率 低Iq; ID: 3; Manufacture: TI; Part Name: DCDC; Part Number: C070202410003; Price: 0.3; Solder: 推荐
M5 = MODE-204P_2
D2-D9 D11 D12 D19 D20 D22-D32 D38-D46 = DI-ESD: DSC1: 双向; DSC2: Vdc=14V; DSC3: Vbr=300V; DSC4: Vc=30V; DSC5: Cj=0.25pF; ERP Number: 1010800023; ID: 2; Manufacture: AEM; Part Name: ESD; Part Number: C040502250002; Price: 0.06
D10 = DI-XI-S: DSC1: VR=30V; DSC2: IF=200mA; DSC3: VF=350mV/10mA; DSC4: IR=0.5uA; ID: 2; Manufacture: 乐山无线电; Part Name: 肖特基二级管; Part Number: C040202220002; Price: 0.05; Solder: 推荐
J3 = J-TF-01A: DSC1: TF卡座 自弹式; DSC3: 贴片; DSC4: TF-01A(韩荣); ID: 2; Part Name: SD卡座; Part Number: J080102980002
J4 = J-A-3P: DSC1: 3p; DSC2: 1.25mm间距; DSC3: 立贴; DSC4: 米黄色胶壳 耐高温; DSC5: A1251WV-S-3P(CJT); ID: 7; Part Name: MX1.25T; Part Number: J020102800059
R18-R24 R39 = R-0402: DSC1: ±1%; DSC2: 1/16W; ID: 552; Part Name: 贴片电阻; Part Number: C011002080552; Price: 0.01
R25 R79 R80 = R-0402: DSC1: ±1%; DSC2: 1/16W; ERP Number: 1010200445; ID: 818; Part Name: 贴片电阻; Part Number: C011002080818; Price: 0.01
R26 R27 R69 R75 = R-0402: DSC1: ±1%; DSC2: 1/16W; ERP Number: 1010200450; ID: 630; Part Name: 贴片电阻; Part Number: C011002080630; Price: 0.01
C64 C65 = C-0402: DSC1: ±5%; DSC2: 50V; DSC3: C0G; ERP Number: 1010200091; ID: 27; Manufacture: 三星|国巨|村田; Part Name: 贴片电容; Part Number: C020102120027; Price: 0.02
D18 D21 = DI-ESD-MKT642U05: DSC2: Vdc=5V; DSC3: Vbr=6V; DSC4: Vc=16V; DSC5: Cj=0.35pF; ID: 8; Manufacture: 米客方德; Part Name: ESD; Part Number: C040502250008; Price: 0.15; Solder: 推荐
J8 J9 = J-USB-4AFx2-DIP_2: DSC1: USB AF 双层 DIP 90° 铁壳 弯脚  白色; DSC2: 17.6*14.5*15.7mm; DSC3: 通孔弯针; DSC4: C2341(LC); ID: 6; Part Name: USB连接器; Part Number: J060102960006
J10-J12 = J-H-4P_0: DSC1: 4p; DSC2: 2.0mm间距; DSC3: 通孔180度直针; DSC4: 米黄色胶壳 耐高温; DSC5: A2001WV-4P(CJT); ID: 13; Part Name: PH; Part Number: J020302820003
L7-L10 L12 L14 L15 = L-CMLS-ACM2012: DSC1: 90uH@100kHz; DSC2: 90Ω@100MHz; DSC3: 400mA; DSC4: DCR=300mΩ; DSC5: -40℃ ~ +125℃; DSC6: SMD_4P,2x1.2mm; ERP Number: 1010200196; ID: 1; Manufacture: 台庆; Part Name: 信号共模电感; Part Number: C060402360001; Price: 0.13
L11 L13 L16-L22 = FB-0603: DSC1: 100Ω@100MHz; DSC2: 3A; DSC3: DCR=30mΩ; DSC4: 电源线; ERP Number: 1010200207; ID: 5; Manufacture: 顺络; Part Name: 贴片磁珠; Part Number: C060502370005; Price: 0.03
R40 R42 R47 R52 R56 R382 = R-0402: DSC1: ±1%; DSC2: 1/16W; ERP Number: 1010200459; ID: 1,059; Part Name: 贴片电阻; Part Number: C011002081059; Price: 0.01
R41 R43 R49 R53 R57 R59 R381 = R-0402: DSC1: ±1%; DSC2: 1/16W; ERP Number: 1010200334; ID: 837; Part Name: 贴片电阻; Part Number: C011002080837; Price: 0.01
R50 R51 R73 R76 R77 = R-0402: DSC1: ±1%; DSC2: 1/16W; ID: 413; Part Name: 贴片电阻; Part Number: C011002080413; Price: 0.01
R54 = R-0402: DSC1: ±1%; DSC2: 1/16W; ID: 789; Part Name: 贴片电阻; Part Number: C011002080789; Price: 0.01
R55 = R-0402: DSC1: ±1%; DSC2: 1/16W; ERP Number: 1010200470; ID: 1,093; Part Name: 贴片电阻; Part Number: C011002081093; Price: 0.01
U6 U7 U9-U12 U40 = U-SY6280AAC: DSC1: 低能耗电源开关; DSC2: 2.4-5.5V 2A; DSC3: 80m?; DSC4: -40~85℃; ERP Number: 1010100222; ID: 1; Manufacture: 矽力杰; Part Name: 功率开关; Part Number: C070402430001; Price: 0.42
U8 = U-FE2.1: DSC1: USB 2.0 HIGH SPEED 7-PORT HUB CONTROLLER; DSC2: 48 PIN LQFP - 7mmX7mm,0.5 Pitch; ID: 21; Manufacture: TERMINUS; Part Name: USB芯片; Part Number: C100202500010
XT1 = XTAL-4P: DSC1: 100Ω; DSC2: ±10ppm; DSC3: 12pF; DSC4: -40℃~+85℃; DSC5: 3.2*2.5mm 4P; ERP Number: 1010700002; ID: 4; Manufacture: 泰晶; Part Name: 贴片无源晶振; Part Number: C050102290004; Price: 0.45
C84 = C-0402: DSC1: ±5%; DSC2: 50V; DSC3: C0G; ERP Number: 1010200149; ID: 45; Manufacture: 三星|国巨|村田; Part Name: 贴片电容; Part Number: C020102120045; Price: 0.01
J15 = J-PJ-316A-6A: DSC1: 3.5mm贴片式耳机座 凸头 6P 单定位柱; DSC2: 14*6*4mm; DSC4: PJ-316A-6A(韩荣); ID: 10; Part Name: 音频耳机座; Part Number: J050502940002
J16 = J-H-2P: DSC1: 2p; DSC2: 2.0mm间距; DSC3: 通孔180度直针; DSC4: 米黄色胶壳 耐高温; DSC5: A2001WV-2P(CJT); ID: 11; Part Name: PH; Part Number: J020302820001
J17 = J-A-4P: DSC1: 4p; DSC2: 2.0mm间距; DSC3: 卧贴; DSC4: 米黄色胶壳 耐高温; DSC5: A2001WR-S-4P(CJT); ID: 28; Part Name: PH; Part Number: J020302820060
Q1 Q2 = S-NPN: DSC1: NPN; DSC2: Ic=100mA; DSC3: Vce=50V; DSC4: 150mW; ERP Number: 1010800049; ID: 2; Manufacture: 长电; Part Name: 数字三极管; Part Number: C030302200002; Price: 0.08
R68 R78 = R-0402: DSC1: ±1%; DSC2: 1/16W; ID: 778; Part Name: 贴片电阻; Part Number: C011002080778; Price: 0.01
TP24-TP27 = TP-TEST: DSC1: 焊盘1mm; DSC2: 无孔; DSC3: 圆形; DSC4: 单面; ID: 3; Part Name: 测试点
U13 = U-NS4205: DSC1: 2*3W @4Ω,3~5.2V，Class D; DSC3: -40~85℃; ERP Number: 1010100190; ID: 2; Manufacture: Nsiway(纳芯威); Part Name: 功放; Part Number: C150102670002; Price: 0.7

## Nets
GND: C3.1 C4.2 C6.1 C7.1 C9.1 C10.1 C11.1 C12.1 C14.1 C17.1 C18.1 C20.1 C21.1 C22.1 C23.1 C25.1 C26.1 C27.1 C30.1 C31.1 C32.1 C33.1 C34.1 C35.1 C52.1 C53.1 C54.1 C55.1 C56.1 C57.1 C58.1 C59.1 C60.1 C61.1 C62.1 C63.1 C64.1 C65.1 C66.1 C67.1 C68.1 C69.1 C70.1 C71.1 C72.1 C73.1 C74.1 C75.1 C76.1 C77.1 C78.1 C79.1 C80.1 C81.1 C82.1 C83.1 C84.1 C85.1 C87.2 C88.2 C90.2 C91.2 C92.1 C93.1 C94.1 C95.1 C486.1 C489.1 C490.1 D2.2(I/O1) D3.2(I/O1) D4.2(I/O1) D5.2(I/O1) D6.2(I/O1) D7.2(I/O1) D8.2(I/O1) D9.2(I/O1) D11.2(I/O1) D12.2(I/O1) D18.3 D18.8 D19.2(I/O1) D20.2(I/O1) D21.3 D21.8 D22.2(I/O1) D23.2(I/O1) D24.2(I/O1) D25.2(I/O1) D26.2(I/O1) D27.2(I/O1) D28.2(I/O1) D29.2(I/O1) D30.2(I/O1) D31.2(I/O1) D32.2(I/O1) D38.2(I/O1) D39.2(I/O1) D40.2(I/O1) D41.2(I/O1) D42.2(I/O1) D43.2(I/O1) D44.2(I/O1) D45.2(I/O1) D46.2(I/O1) J3.6(VSS) J3.10(G1) J3.11(G2) J3.12(G3) J3.13(G4) J4.3 J4.4 J4.5 J8.4(1GND) J8.13(2GND) J8.S1(MH1) J8.S2(MH2) J8.S3(MH3) J8.S4(MH4) J9.4(1GND) J9.13(2GND) J9.S1(MH1) J9.S2(MH2) J9.S3(MH3) J9.S4(MH4) J10.4 J11.4 J12.4 J15.1(GND) J16.1 J17.5 J17.6 L50.4 LED1.2 LED1.4 M5.4(GND1) M5.5(GND2) M5.14(GND3) M5.38(GND4) M5.98(GND5) M5.105(GND6) M5.127(GND7) M5.152(GND8) M5.179(GND9) M5.194(GND10) Q1.2 Q2.2 R5.2 R6.2 R10.2 R15.2 R17.2 R40.2 R41.2 R42.2 R43.2 R45.2 R47.2 R49.2 R52.2 R53.2 R54.2 R56.2 R57.2 R59.2 R71.2 R77.2 R369.2 R381.2 R382.2 U1.3(GND) U2.2(GND) U6.2(GND) U7.2(GND) U8.10(VSS1) U8.24(VS_PLL) U8.39(VSS) U9.2(GND) U10.2(GND) U11.2(GND) U12.2(GND) U13.2(PGND1) U13.11(GND1) U13.15(PGND2) U39.3(GND) U40.2(GND) XT1.2 XT1.4 ; also on sheet 9 10 11 12 13 14 15 16 17 18 19 20 21 22 23
GND_EARTH: H1.1 H2.1 H3.1 H4.1 ; also on sheet 15 16
GND_IN: C488.1 D1.A J1.1 J1.2 J2.2 J2.3 L50.1 R369.1
VBUSM: R44.1 R45.1 U8.41(VBUSM)
VCC3V3_SD: C35.2 D2.1(I/O2) J3.4(VDD) M5.69(VCC3V3_SD)
VCC5V0_SYS: C17.2 C18.2 C24.2 C25.2 C26.2 C27.2 C30.2 C31.2 C32.2 C33.2 C486.2 L3.2 L13.1 L21.1 M5.1(VCC5V0_RTC) M5.2(VCC5V0_SYS1) M5.3(VCC5V0_SYS2) R7.1 R13.1 R44.2 U2.4(VIN) ; also on sheet 10 11 12 13 20 22
VCC5V0_USB_FE_D1: C54.2 D20.1(I/O2) J8.10(2VBUS) U7.1(VOUT)
VCC5V0_USB_FE_D2: C57.2 D22.1(I/O2) J9.1(1VBUS) U9.1(VOUT)
VCC5V0_USB_FE_D3: C61.2 D23.1(I/O2) J9.10(2VBUS) U10.1(VOUT)
VCC5V0_USB_FE_D4: C67.2 D24.1(I/O2) J10.1 U11.1(VOUT)
VCC5V0_USB_FE_D5: C489.2 D27.1(I/O2) J11.1 U40.1(VOUT)
VCC5V0_USB_FE_D6: C78.2 D30.1(I/O2) J12.1 U12.1(VOUT)
VCC5V0_USB_HOST3: C52.2 D19.1(I/O2) J8.1(1VBUS) U6.1(VOUT)
VCC12V_DC_IN: F1.1 J1.3 J1.4 J2.4
VCC12V_DCIN: C3.2 C4.1 C6.2 C7.2 C22.2 C23.2 L50.3 R3.1 R368.2 U1.1(IN) U39.1(IN) ; also on sheet 10 13
VCC_1V8: M5.103(VCC_1V8) ; also on sheet 13 14 15 16 21 23
VCC_1V8_HUB: C63.2 C74.2 C75.2 C76.2 U8.6(VD18_1) U8.21(VD_PLL) U8.25(VD18_O) U8.28(VD18_1)
VCC_3V3: M5.104(VCC_3V3) R14.1
VCC_3V3_HUB: C59.2 C66.2 C68.2 C69.2 C70.2 C71.2 C72.2 C73.2 L11.2 R46.2 R48.1 U8.9(VDD33_O) U8.15(VD33_1) U8.20(VD33_1) U8.26(VD33_1) U8.31(VD33_1) U8.36(VD33_1) U8.42(VD33_1)
VCC_5V_HUB: C58.2 L13.2 U8.8(VD5_1)
VCCA_CODEC: C94.2 C95.2 L22.2 U13.6(VDD1) U13.9(VDD2)
VCCIO_ACODEC: L16.2 R69.2 R75.1
VDD_3V3: C19.2 C20.2 C21.2 L2.2 L11.1 L16.1 L22.1 R9.1 R12.1 R25.1 R72.1 ; also on sheet 9 10 11 12 13 14 15 16 17 18 22 23
VDD_USB_5V: C8.2 C9.2 C10.2 C11.2 C53.2 C55.2 C56.2 C62.2 C77.2 C79.2 C490.2 L1.2 R4.1 U6.5(IN) U7.5(IN) U9.5(IN) U10.5(IN) U11.5(IN) U12.4(EN) U12.5(IN) U40.5(IN) ; also on sheet 9 19 21
4G_5G_RESET_GPIO3_A4: M5.123(LCDC_D11/VOP_BT1120_D3/GMAC1_RXD2_M0/I2S3_LRCK_M0/SDMMC2_D3_M1/GPIO3_A4_d) ; also on sheet 20
BT_REG_ON_H_GPIO3_A7: M5.120(LCDC_D14/VOP_BT1120_D5/GMAC1_RXCLK_M0/SDMMC2_DET_M1/GPIO3_A7_d) ; also on sheet 23
BT_WAKE_HOST_H_GPIO3_A1: M5.126(LCDC_D8/VOP_BT1120_D0/SPI1_CS0_M1/PCIE30X1_PERSTn_M1/SDMMC2_D0_M1/GPIO3_A1_d) ; also on sheet 23
CAN1_RX_M0: M5.36(I2C3_SDA_M0/UART3_RX_M0/CAN1_RX_M0/AUDIOPWM_LOUT_P/ACODEC_ADC_DATA/GPIO1_A0_u) ; also on sheet 22
CAN1_TX_M0: M5.37(I2C3_SCL_M0/UART3_TX_M0/CAN1_TX_M0/AUDIOPWM_LOUT_N/ACODEC_ADC_CLK/GPIO1_A1_u) ; also on sheet 22
CAN2_RX_M0: M5.75(I2C2_SDA_M1/EBC_GDSP/CAN2_RX_M0/ISP_FLASH_TRIGIN/VOP_BT656_CLK_M1/GPIO4_B4_d) ; also on sheet 22
CAN2_TX_M0: M5.74(I2C2_SCL_M1/EBC_SDSHR/CAN2_TX_M0/I2S1_SDO3_M1/GPIO4_B5_d) ; also on sheet 22
CIF_CLKOUT_SOC: M5.71(CIF_CLKOUT/EBC_GDCLK/PWM11_IR_M1/GPIO4_C0_d) ; also on sheet 14
CIF_RST_GPIO3_A3: M5.124(LCDC_D10/VOP_BT1120_D2/GMAC1_TXD3_M0/I2S3_SCLK_M0/SDMMC2_D2_M1/GPIO3_A3_d) ; also on sheet 14
EDP_HPDIN_M1: M5.21(PWM3_IR/EDP_HPDIN_M1/PCIE30X1_WAKEn_M0/MCU_JTAG_TMS/GPIO0_C2_d) ; also on sheet 10
EDP_PWM4: M5.22(PWM4/VOP_PWM_M0/PCIE30X1_PERSTn_M0/MCU_JTAG_TRSTn/GPIO0_C3_d) ; also on sheet 10 12
EDP_TX_AUXN: M5.197(EDP_TX_AUXN) ; also on sheet 10
EDP_TX_AUXP: M5.198(EDP_TX_AUXP) ; also on sheet 10
EDP_TX_D0N: M5.203(EDP_TX_D0N) ; also on sheet 10
EDP_TX_D0P: M5.204(EDP_TX_D0P) ; also on sheet 10
EDP_TX_D1N: M5.201(EDP_TX_D1N) ; also on sheet 10
EDP_TX_D1P: M5.202(EDP_TX_D1P) ; also on sheet 10
EDP_TX_D2N: M5.199(EDP_TX_D2N) ; also on sheet 10
EDP_TX_D2P: M5.200(EDP_TX_D2P) ; also on sheet 10
EDP_TX_D3N: M5.195(EDP_TX_D3N) ; also on sheet 10
EDP_TX_D3P: M5.196(EDP_TX_D3P) ; also on sheet 10
EXT_EN: M5.7(EXT_EN) R16.1
FE2.1_DM0: R51.1 U8.29(DM_I)
FE2.1_DM1: L8.2 U8.18(DM1)
FE2.1_DM1_: D18.5 D18.6 J8.11(2D-) L8.3
FE2.1_DM2: L9.2 U8.16(DM2)
FE2.1_DM2_: D21.2 D21.9 J9.2(1D-) L9.3
FE2.1_DM3: L10.2 U8.13(DM3)
FE2.1_DM3_: D21.5 D21.6 J9.11(2D-) L10.3
FE2.1_DM4: L12.2 U8.11(DM4)
FE2.1_DM4_: D25.1(I/O2) J10.2 L12.3
FE2.1_DM5: L14.2 U8.34(DM5)
FE2.1_DM5_: D28.1(I/O2) J11.2 L14.3
FE2.1_DM6: L15.2 U8.32(DM6)
FE2.1_DM6_: D31.1(I/O2) J12.2 L15.3
FE2.1_DM7: U8.37(DM7) ; also on sheet 20
FE2.1_DP0: R50.1 U8.30(DP_1)
FE2.1_DP1: L8.1 U8.19(DP1)
FE2.1_DP1_: D18.4 D18.7 J8.12(2D+) L8.4
FE2.1_DP2: L9.1 U8.17(DP2)
FE2.1_DP2_: D21.1 D21.10 J9.3(1D+) L9.4
FE2.1_DP3: L10.1 U8.14(DP3)
FE2.1_DP3_: D21.4 D21.7 J9.12(2D+) L10.4
FE2.1_DP4: L12.1 U8.12(DP4)
FE2.1_DP4_: D26.1(I/O2) J10.3 L12.4
FE2.1_DP5: L14.1 U8.35(DP5)
FE2.1_DP5_: D29.1(I/O2) J11.3 L14.4
FE2.1_DP6: L15.1 U8.33(DP6)
FE2.1_DP6_: D32.1(I/O2) J12.3 L15.4
FE2.1_DP7: U8.38(DP7) ; also on sheet 20
FE21_XIN: C64.2 R55.1 U8.22(XIN) XT1.1
FE21_XOUT: C65.2 R55.2 U8.23(XOUT) XT1.3
GMAC0_INT/PMEB_GPIO3_B0: M5.119(LCDC_D15/VOP_BT1120_D6/ETH1_REFCLKO_25M_M0/SDMMC2_PWREN_M1/GPIO3_B0_d) ; also on sheet 15
GMAC0_MCLKINOUT: M5.54(I2S2_SCLK_TX_M0/GMAC0_MCLKINOUT/UART7_CTSn_M0/SPI2_MISO_M0/GPIO2_C2_d) ; also on sheet 15
GMAC0_MDC: M5.55(I2S2_LRCK_TX_M0/GMAC0_MDC/UART9_RTSn_M0/SPI2_MOSI_M0/GPIO2_C3_d) ; also on sheet 15
GMAC0_MDIO: M5.56(I2S2_SDO_M0/GMAC0_MDIO/UART9_CTSn_M0/SPI2_CS0_M0/GPIO2_C4_d) ; also on sheet 15
GMAC0_RSTn_GPIO3_A5: M5.122(LCDC_D12/VOP_BT1120_D4/GMAC1_RXD3_M0/I2S3_SDO_M0/SDMMC2_CMD_M1/GPIO3_A5_d) ; also on sheet 15
GMAC0_RXCLK: M5.41(SDMMC1_D2/GMAC0_RXCLK/UART7_RX_M0/GPIO2_A5_u) ; also on sheet 15
GMAC0_RXD0: M5.50(GMAC0_RXD0/UART1_CTSn_M0/SPI1_MISO_M0/GPIO2_B6_u) ; also on sheet 15
GMAC0_RXD1: M5.51(I2S2_SCLK_RX_M0/GMAC0_RXD1/UART6_RTSn_M0/SPI1_MOSI_M0/GPIO2_B7_d) ; also on sheet 15
GMAC0_RXD2: M5.39(SDMMC1_D0/GMAC0_RXD2/UART6_RX_M0/GPIO2_A3_u) ; also on sheet 15
GMAC0_RXD3: M5.40(SDMMC1_D1/GMAC0_RXD3/UART6_TX_M0/GPIO2_A4_u) ; also on sheet 15
GMAC0_RXDV_CRS: M5.52(I2S2_LRCK_RX_M0/GMAC0_RXDV_CRS/UART6_CTSn_M0/SPI1_CS0_M0/GPIO2_C0_d) ; also on sheet 15
GMAC0_TXCLK: M5.44(SDMMC1_CLK/GMAC0_TXCLK/UART9_TX_M0/GPIO2_B0_d) ; also on sheet 15
GMAC0_TXD0: M5.47(GMAC0_TXD0/UART1_RX_M0/GPIO2_B3_u) ; also on sheet 15
GMAC0_TXD1: M5.48(GMAC0_TXD1/UART1_TX_M0/GPIO2_B4_u) ; also on sheet 15
GMAC0_TXD2: M5.42(SDMMC1_D3/GMAC0_TXD2/UART7_TX_M0/GPIO2_A6_u) ; also on sheet 15
GMAC0_TXD3: M5.43(SDMMC1_CMD/GMAC0_TXD3/UART9_RX_M0/GPIO2_A7_u) ; also on sheet 15
GMAC0_TXEN: M5.49(GMAC0_TXEN/UART1_RTSn_M0/SPI1_CLK_M0/GPIO2_B5_u) ; also on sheet 15
GMAC1_INT/PMEB_GPIO3_C1: M5.110(LCDC_HSYNC/VOP_BT1120_D13/SPI1_MOSI_M1/PCIE20_PERSTn_M1/I2S1_SDO2_M2/GPIO3_C1_d) ; also on sheet 16
GMAC1_MCLKINOUT_M1: M5.70(CIF_CLKIN/EBC_SDCLK/GMAC1_MCLKINOUT_M1/UART1_CTSn_M1/I2S2_SCLK_RX_M1/GPIO4_C1_d) ; also on sheet 16
GMAC1_MDC_M1: M5.73(CIF_HREF/EBC_SDLE/GMAC1_MDC_M1/UART1_RTSn_M1/I2S2_MCLK_M1/GPIO4_B6_d) ; also on sheet 16
GMAC1_MDIO_M1: M5.72(CIF_VSYNC/EBC_SDOE/GMAC1_MDIO_M1/I2S2_SCLK_TX_M1/GPIO4_B7_d) ; also on sheet 16
GMAC1_RSTn_GPIO3_A6: M5.121(LCDC_D13/VOP_BT1120_CLK/GMAC1_TXCLK_M0/I2S3_SDI_M0/SDMMC2_CLK_M1/GPIO3_A6_d) ; also on sheet 16
GMAC1_RXCLK_M1: M5.84(CIF_D13/EBC_SDDO13/GMAC1_RXCLK_M1/UART7_RX_M2/PDM_SDI3_M1/GPIO4_A3_d) ; also on sheet 16
GMAC1_RXD0_M1: M5.80(CAM_CLKOUT0/EBC_SDCE1/GMAC1_RXD0_M1/SPI3_CS1_M0/I2S1_LRCK_RX_M1/GPIO4_A7_d) ; also on sheet 16
GMAC1_RXD1_M1: M5.79(CAM_CLKOUT1/EBC_SDCE2/GMAC1_RXD1_M1/SPI3_MISO_M0/I2S1_SDO1_M1/GPIO4_B0_d) ; also on sheet 16
GMAC1_RXD2_M1: M5.86(CIF_D11/EBC_SDDO11/GMAC1_RXD2_M1/PDM_SDI1_M1/GPIO4_A1_d) ; also on sheet 16
GMAC1_RXD3_M1: M5.85(CIF_D12/EBC_SDDO12/GMAC1_RXD3_M1/UART7_TX_M2/PDM_SDI2_M1/GPIO4_A2_d) ; also on sheet 16
GMAC1_RXDV_CRS_M1: M5.78(ISP_PRELIGHT_TRIG/EBC_SDCE3/GMAC1_RXDV_CRS_M1/I2S1_SDO2_M1/GPIO4_B1_d) ; also on sheet 16
GMAC1_TXCLK_M1: M5.87(CIF_D10/EBC_SDDO10/GMAC1_TXCLK_M1/PDM_CLK1_M1/GPIO4_A0_d) ; also on sheet 16
GMAC1_TXD0_M1: M5.83(CIF_D14/EBC_SDDO14/GMAC1_TXD0_M1/UART9_TX_M2/I2S2_LRCK_TX_M1/GPIO4_A4_d) ; also on sheet 16
GMAC1_TXD1_M1: M5.82(CIF_D15/EBC_SDDO15/GMAC1_TXD1_M1/UART9_RX_M2/I2S2_LRCK_RX_M1/GPIO4_A5_d) ; also on sheet 16
GMAC1_TXD2_M1: M5.89(CIF_D8/EBC_SDDO8/GMAC1_TXD2_M1/UART1_TX_M1/PDM_CLK0_M1/GPIO3_D6_d) ; also on sheet 16
GMAC1_TXD3_M1: M5.88(CIF_D9/EBC_SDDO9/GMAC1_TXD3_M1/UART1_RX_M1/PDM_SDI0_M1/GPIO3_D7_d) ; also on sheet 16
GMAC1_TXEN_M1: M5.81(ISP_FLASHTRIGOUT/EBC_SDCE0/GMAC1_TXEN_M1/SPI3_CS0_M0/I2S1_SCLK_RX_M1/GPIO4_A6_d) ; also on sheet 16
HDMI_TX_CLKN: M5.153(HDMI_TX_CLKN) ; also on sheet 9
HDMI_TX_CLKP: M5.154(HDMI_TX_CLKP) ; also on sheet 9
HDMI_TX_D0N: M5.155(HDMI_TX_D0N) ; also on sheet 9
HDMI_TX_D0P: M5.156(HDMI_TX_D0P) ; also on sheet 9
HDMI_TX_D1N: M5.157(HDMI_TX_D1N) ; also on sheet 9
HDMI_TX_D1P: M5.158(HDMI_TX_D1P) ; also on sheet 9
HDMI_TX_D2N: M5.159(HDMI_TX_D2N) ; also on sheet 9
HDMI_TX_D2P: M5.160(HDMI_TX_D2P) ; also on sheet 9
HDMI_TX_HPDIN: M5.148(HDMI_TX_HPDIN) ; also on sheet 9
HDMITX_CEC_M0: M5.151(HDMITX_CEC_M0/SPI3_CS1_M1/GPIO4_D1_u) ; also on sheet 9
HOST_WAKE_BT_H_GPIO3_A2: M5.125(LCDC_D9/VOP_BT1120_D1/GMAC1_TXD2_M0/I2S3_MCLK_M0/SDMMC2_D1_M1/GPIO3_A2_d) ; also on sheet 23
HP_DET_H_GPIO0_C5: C82.2 M5.24(PWM6/SPI0_MISO_M0/PCIE30X2_WAKEn_M0/GPIO0_C5_d) R72.2 R74.1
HP_SNS: M5.10(HP_SNS) R77.1
HPL_OUT: C86.2 M5.9(HPL_OUT) R73.1
HPR_OUT: C89.2 M5.11(HPR_OUT) R76.1
HUB_RST_: C60.2 R39.2 R48.2 U8.40(XRSTJ)
I2C1_SCL: M5.32(I2C1_SCL/CAN0_TX_M0/PCIE30X1_BUTTONRSTn/MCU_JTAG_TDO/GPIO0_B3_u) ; also on sheet 17 18
I2C1_SDA: M5.33(I2C1_SDA/CAN0_RX_M0/PCIE20_BUTTONRSTn/MCU_JTAG_TCK/GPIO0_B4_u) ; also on sheet 17 18
I2C2_SCL_M0: M5.34(I2C2_SCL_M0/SPI0_CLK_M0/PCIE20_WAKEn_M0/PWM1_M1/GPIO0_B5_u) ; also on sheet 18
I2C2_SDA_M0: M5.35(I2C2_SDA_M0/SPI0_MOSI_M0/PCIE20_PERSTn_M0/PWM2_M1/GPIO0_B6_u) ; also on sheet 18
I2C3_SCL_M1: M5.114(LCDC_D20/VOP_BT1120_D11/GMAC1_TXD0_M0/I2C3_SCL_M1/PWM10_M0/GPIO3_B5_d) ; also on sheet 12
I2C3_SDA_M1: M5.113(LCDC_D21/VOP_BT1120_D12/GMAC1_TXD1_M0/I2C3_SDA_M1/PWM11_IR_M0/GPIO3_B6_d) ; also on sheet 12
I2C4_SCL_M0: M5.76(I2C4_SCL_M0/EBC_GDOE/ETH1_REFCLKO_25M_M1/SPI3_CLK_M0/I2S2_SDO_M1/GPIO4_B3_d) ; also on sheet 14
I2C4_SDA_M0: M5.77(I2C4_SDA_M0/EBC_VCOM/GMAC1_RXER_M1/SPI3_MOSI_M0/I2S2_SDI_M1/GPIO4_B2_d) ; also on sheet 14
I2C5_SCL-HDMI: M5.150(HDMITX_SCL/I2C5_SCL_M1/GPIO4_C7_u) ; also on sheet 9
I2C5_SDA-HDMI: M5.149(HDMITX_SDA/I2C5_SDA_M1/GPIO4_D0_u) ; also on sheet 9
LVDS_PWM5: M5.23(PWM5/SPI0_CS1_M0/UART0_RTSn/GPIO0_C4_d) ; also on sheet 11 13
MIC1_INN: D41.1(I/O2) J15.4(~{DET}) M5.13(MIC1_INN) R68.1 R70.1
MIC1_INP: C84.2 D42.1(I/O2) J16.2 M5.12(MIC1_INP) R78.2
MIPI_CAM0_PDN_L_GPIO2_C1: M5.53(I2S2_MCLK_M0/ETH0_REFCLKO_25M/UART7_RTSn_M0/SPI2_CLK_M0/GPIO2_C1_d) ; also on sheet 14
MIPI_CSI_RX_CLK0N: M5.170(MIPI_CSI_RX_CLK0N/PCIE30_REFCLKN_IN) ; also on sheet 14
MIPI_CSI_RX_CLK0P: M5.169(MIPI_CSI_RX_CLK0P/PCIE30_REFCLKP_IN) ; also on sheet 14
MIPI_CSI_RX_CLK1N: M5.172(MIPI_CSI_RX_CLK1N)
MIPI_CSI_RX_CLK1P: M5.171(MIPI_CSI_RX_CLK1P)
MIPI_CSI_RX_D0N: M5.162(MIPI_CSI_RX_D0N/PCIE30_TX0N) ; also on sheet 14
MIPI_CSI_RX_D0P: M5.161(MIPI_CSI_RX_D0P/PCIE30_TX0P) ; also on sheet 14
MIPI_CSI_RX_D1N: M5.164(MIPI_CSI_RX_D1N/PCIE30_TX1N) ; also on sheet 14
MIPI_CSI_RX_D1P: M5.163(MIPI_CSI_RX_D1P/PCIE30_TX1P) ; also on sheet 14
MIPI_CSI_RX_D2N: M5.166(MIPI_CSI_RX_D2N/PCIE30_RX0N) ; also on sheet 14
MIPI_CSI_RX_D2P: M5.165(MIPI_CSI_RX_D2P/PCIE30_RX0P) ; also on sheet 14
MIPI_CSI_RX_D3N: M5.168(MIPI_CSI_RX_D3N/PCIE30_RX1N) ; also on sheet 14
MIPI_CSI_RX_D3P: M5.167(MIPI_CSI_RX_D3P/PCIE30_RX1P) ; also on sheet 14
MIPI_DSI_TX0_CLKN: M5.142(MIPI_DSI_TX0_CLKN/LVDS_TX0_CLKN) ; also on sheet 11 13
MIPI_DSI_TX0_CLKP: M5.143(MIPI_DSI_TX0_CLKP/LVDS_TX0_CLKP) ; also on sheet 11 13
MIPI_DSI_TX0_D0N: M5.146(MIPI_DSI_TX0_D0N/LVDS_TX0_D0N) ; also on sheet 11 13
MIPI_DSI_TX0_D0P: M5.147(MIPI_DSI_TX0_D0P/LVDS_TX0_D0P) ; also on sheet 11 13
MIPI_DSI_TX0_D1N: M5.144(MIPI_DSI_TX0_D1N/LVDS_TX0_D1N) ; also on sheet 11 13
MIPI_DSI_TX0_D1P: M5.145(MIPI_DSI_TX0_D1P/LVDS_TX0_D1P) ; also on sheet 11 13
MIPI_DSI_TX0_D2N: M5.140(MIPI_DSI_TX0_D2N/LVDS_TX0_D2N) ; also on sheet 11 13
MIPI_DSI_TX0_D2P: M5.141(MIPI_DSI_TX0_D2P/LVDS_TX0_D2P) ; also on sheet 11 13
MIPI_DSI_TX0_D3N: M5.138(MIPI_DSI_TX0_D3N/LVDS_TX0_D3N) ; also on sheet 11 13
MIPI_DSI_TX0_D3P: M5.139(MIPI_DSI_TX0_D3P/LVDS_TX0_D3P) ; also on sheet 11 13
MIPI_DSI_TX1_CLKN: M5.132(MIPI_DSI_TX1_CLKN) ; also on sheet 12
MIPI_DSI_TX1_CLKP: M5.133(MIPI_DSI_TX1_CLKP) ; also on sheet 12
MIPI_DSI_TX1_D0N: M5.136(MIPI_DSI_TX1_D0N) ; also on sheet 12
MIPI_DSI_TX1_D0P: M5.137(MIPI_DSI_TX1_D0P) ; also on sheet 12
MIPI_DSI_TX1_D1N: M5.134(MIPI_DSI_TX1_D1N) ; also on sheet 12
MIPI_DSI_TX1_D1P: M5.135(MIPI_DSI_TX1_D1P) ; also on sheet 12
MIPI_DSI_TX1_D2N: M5.130(MIPI_DSI_TX1_D2N) ; also on sheet 12
MIPI_DSI_TX1_D2P: M5.131(MIPI_DSI_TX1_D2P) ; also on sheet 12
MIPI_DSI_TX1_D3N: M5.128(MIPI_DSI_TX1_D3N) ; also on sheet 12
MIPI_DSI_TX1_D3P: M5.129(MIPI_DSI_TX1_D3P) ; also on sheet 12
nSD_CD: D8.1(I/O2) J3.9(CD) R24.2
PCA9539_INT_GPIO4_C4: M5.29(EDP_HPDIN_M0/SPDIF_TX_M2/SATA2_ACT_LED/PCIE30X2_PERSTn_M2/I2S3_LRCK_M1/GPIO4_C4_d) ; also on sheet 17
PCA9539_IO0_1: R39.1 ; also on sheet 17
PCA9539_IO0_2: R40.1 U6.4(EN) ; also on sheet 17
PCA9539_IO0_3: R42.1 U7.4(EN) ; also on sheet 17
PCA9539_IO0_4: R47.1 U9.4(EN) ; also on sheet 17
PCA9539_IO0_5: R52.1 U10.4(EN) ; also on sheet 17
PCA9539_IO0_6: R56.1 U11.4(EN) ; also on sheet 17
PCA9539_IO1_0: Q1.1 ; also on sheet 17
PCA9539_IO1_1: Q2.1 ; also on sheet 17
PCA9539_IO1_4: R382.1 U40.4(EN) ; also on sheet 17
PCIE20_REFCLKN: M5.178(PCIE20_REFCLKN) ; also on sheet 20
PCIE20_REFCLKP: M5.177(PCIE20_REFCLKP) ; also on sheet 20
PCIE20_RXN: M5.176(PCIE20_RXN/SATA2_RXN/QSGMII_RXN_M1) ; also on sheet 20
PCIE20_RXP: M5.175(PCIE20_RXP/SATA2_RXP/QSGMII_RXP_M1) ; also on sheet 20
PCIE20_TXN: M5.174(PCIE20_TXN/SATA2_TXN/QSGMII_TXN_M1) ; also on sheet 20
PCIE20_TXP: M5.173(PCIE20_TXP/SATA2_TXP/QSGMII_TXP_M1) ; also on sheet 20
PWM7_IR: M5.25(PWM7_IR/SPI0_CS0_M0/PCIE30X2_PERSTn_M0/GPIO0_C6_d) ; also on sheet 21
REXT: R54.1 U8.27(REXT)
RK809_PWRON: M5.8(RK809_PWRON) ; also on sheet 21
RK809_VDC: C14.2 M5.6(RK809_VDC) R7.2 R10.1
SARADC_VIN0_KEY/RECOVERY: M5.15(SARADC_VIN0_KEY/RECOVERY) ; also on sheet 21
SARADC_VIN2_HP_HOOK: C81.2 M5.16(SARADC_VIN2_HP_HOOK) R70.2 R71.1 ; also on sheet 21
SARADC_VIN4: M5.17(SARADC_VIN4) ; also on sheet 21
SARADC_VIN5: M5.18(SARADC_VIN5) ; also on sheet 21
SD_CLK: C34.2 D9.1(I/O2) J3.5(CLK) R21.2
SD_CMD: D7.1(I/O2) J3.3(CMD) R20.2
SD_D0: D3.1(I/O2) J3.7(DATA0) R22.2
SD_D1: D4.1(I/O2) J3.8(DATA1) R23.2
SD_D2: D5.1(I/O2) J3.1(DATA2) R18.2
SD_D3: D6.1(I/O2) J3.2(CD/DATA3) R19.2
SDMMC0_CLK: M5.63(SDMMC0_CLK/TEST_CLKOUT/UART5_TX_M0/CAN0_RX_M1/GPIO2_A2_d) R21.1
SDMMC0_CMD: M5.64(SDMMC0_CMD/PWM10_M1/UART5_RX_M0/CAN0_TX_M1/GPIO2_A1_u) R20.1
SDMMC0_D0: M5.68(SDMMC0_D0/UART2_TX_M1/UART6_TX_M1/PWM8_M1/GPIO1_D5_u) R22.1
SDMMC0_D1: M5.67(SDMMC0_D1/UART2_RX_M1/UART6_RX_M1/PWM9_M1/GPIO1_D6_u) R23.1
SDMMC0_D2: M5.66(SDMMC0_D2/ARMJTAG_TCK/UART5_CTSn_M0/GPIO1_D7_u) R18.1
SDMMC0_D3: M5.65(SDMMC0_D3/ARMJTAG_TMS/UART5_RTSn_M0/GPIO2_A0_u) R19.1
SDMMC0_DET_L: M5.62(SDMMC0_DET/SATA_CP_DET/PCIE30X1_CLKREQn_M0/GPIO0_A4_u) R24.1
SDMMC2_CLK_M0: M5.92(CIF_D5/EBC_SDDO5/SDMMC2_CLK_M0/I2S1_SDI1_M1/VOP_BT656_D5_M1/GPIO3_D3_d) ; also on sheet 23
SDMMC2_CMD_M0: M5.93(CIF_D4/EBC_SDDO4/SDMMC2_CMD_M0/I2S1_SDI0_M1/VOP_BT656_D4_M1/GPIO3_D2_d) ; also on sheet 23
SDMMC2_D0_M0: M5.97(CIF_D0/EBC_SDDO0/SDMMC2_D0_M0/I2S1_MCLK_M1/VOP_BT656_D0_M1/GPIO3_C6_d) ; also on sheet 23
SDMMC2_D1_M0: M5.96(CIF_D1/EBC_SDDO1/SDMMC2_D1_M0/I2S1_SCLK_TX_M1/VOP_BT656_D1_M1/GPIO3_C7_d) ; also on sheet 23
SDMMC2_D2_M0: M5.95(CIF_D2/EBC_SDDO2/SDMMC2_D2_M0/I2S1_LRCK_TX_M1/VOP_BT656_D2_M1/GPIO3_D0_d) ; also on sheet 23
SDMMC2_D3_M0: M5.94(CIF_D3/EBC_SDDO3/SDMMC2_D3_M0/I2S1_SDO0_M1/VOP_BT656_D3_M1/GPIO3_D1_d) ; also on sheet 23
SPI3_CLK_M1: M5.27(PWM14_M1/SPI3_CLK_M1/CAN1_RX_M1/PCIE30X2_CLKREQn_M2/I2S3_MCLK_M1/GPIO4_C2_d) ; also on sheet 21
SPI3_CS0_M1: M5.31(PWM13_M1/SPI3_CS0_M1/SATA0_ACT_LED/UART9_RX_M1/I2S3_SDI_M1/GPIO4_C6_d) ; also on sheet 21
SPI3_MISO_M1: M5.30(PWM12_M1/SPI3_MISO_M1/SATA1_ACT_LED/UART9_TX_M1/I2S3_SDO_M1/GPIO4_C5_d) ; also on sheet 21
SPI3_MOSI_M1: M5.28(PWM15_IR_M1/SPI3_MOSI_M1/CAN1_TX_M1/PCIE30X2_WAKEn_M2/I2S3_SCLK_M1/GPIO4_C3_d) ; also on sheet 21
SPK_5V: C92.2 C93.2 L21.2 U13.4(PVDD1) U13.13(PVDD2)
SPK_CTL_H_: Q1.3 U13.12(~{SD})
SPK_MUTE_H_: Q2.3 U13.5(~{MUTE})
SYS_LED_GPIO0_C7: M5.26(HDMITX_CEC_M1/PWM0_M1/UART0_CTSn/GPIO0_C7_d) R8.1
TP_INT_L_GPIO3_B4: M5.115(LCDC_D19/VOP_BT1120_D10/GMAC1_RXER_M0/I2C5_SDA_M0/PDM_SDI1_M2/GPIO3_B4_d) ; also on sheet 12
TP_RST_L_GPIO3_B3: M5.116(LCDC_D18/VOP_BT1120_D9/GMAC1_RXDV_CRS_M0/I2C5_SCL_M0/PDM_SDI0_M2/GPIO3_B3_d) ; also on sheet 12
UART0_RX: M5.19(PWM1_M0/GPUAVS/UART0_RX/GPIO0_C0_d) ; also on sheet 22
UART0_TX: M5.20(PWM2_M0/NPUAVS/UART0_TX/MCU_JTAG_TDI/GPIO0_C1_d) ; also on sheet 22
UART2_RX_M0: M5.60(UART2_RX_M0/GPIO0_D0_u) R26.1
UART2_TX_M0: M5.59(UART2_TX_M0/GPIO0_D1_u) R27.1
UART3_RX_M1: M5.111(LCDC_D23/PWM13_M0/GMAC1_MCLKINOUT_M0/UART3_RX_M1/PDM_SDI3_M2/GPIO3_C0_d) ; also on sheet 22
UART3_TX_M1: M5.112(LCDC_D22/PWM12_M0/GMAC1_TXEN_M0/UART3_TX_M1/PDM_SDI2_M2/GPIO3_B7_d) ; also on sheet 22
UART4_RX_M1: M5.118(LCDC_D16/VOP_BT1120_D7/GMAC1_RXD0_M0/UART4_RX_M1/PWM8_M0/GPIO3_B1_d) ; also on sheet 22
UART4_TX_M1: M5.117(LCDC_D17/VOP_BT1120_D8/GMAC1_RXD1_M0/UART4_TX_M1/PWM9_M0/GPIO3_B2_d) ; also on sheet 22
UART5_RX_M1: M5.108(LCDC_DEN/VOP_BT1120_D15/SPI1_CLK_M1/UART5_RX_M1/I2S1_SCLK_RX_M2/GPIO3_C3_d) ; also on sheet 22
UART5_TX_M1: M5.109(LCDC_VSYNC/VOP_BT1120_D14/SPI1_MISO_M1/UART5_TX_M1/I2S1_SDO3_M2/GPIO3_C2_d) ; also on sheet 22
UART7_RX_M1: M5.106(PWM15_IR_M0/SPDIF_TX_M1/GMAC1_MDIO_M0/UART7_RX_M1/I2S1_LRCK_RX_M2/GPIO3_C5_d) ; also on sheet 22
UART7_TX_M1: M5.107(PWM14_M0/VOP_PWM_M1/GMAC1_MDC_M0/UART7_TX_M1/PDM_CLK1_M2/GPIO3_C4_d) ; also on sheet 22
UART8_CTSn_M0: M5.46(SDMMC1_DET/I2C4_SCL_M1/UART8_CTSn_M0/CAN2_TX_M1/GPIO2_B2_u) ; also on sheet 23
UART8_RTSn_M0: M5.45(SDMMC1_PWREN/I2C4_SDA_M1/UART8_RTSn_M0/CAN2_RX_M1/GPIO2_B1_d) ; also on sheet 23
UART8_RX_M0: M5.58(CLK32K_OUT1/UART8_RX_M0/SPI1_CS1_M0/GPIO2_C6_d) ; also on sheet 23
UART8_TX_M0: M5.57(I2S2_SDI_M0/GMAC0_RXER/UART8_TX_M0/SPI2_CS1_M0/GPIO2_C5_d) ; also on sheet 23
USB2_HOST2_DM: M5.99(USB2_HOST2_DM) R51.2
USB2_HOST2_DP: M5.100(USB2_HOST2_DP) R50.2
USB2_HOST3_DM: L7.2 M5.101(USB2_HOST3_DM)
USB2_HOST3_DM_: D18.2 D18.9 J8.2(1D-) L7.3
USB2_HOST3_DP: L7.1 M5.102(USB2_HOST3_DP)
USB2_HOST3_DP_: D18.1 D18.10 J8.3(1D+) L7.4
USB3_HOST1_DM: M5.182(USB3_HOST1_DM) ; also on sheet 19
USB3_HOST1_DP: M5.183(USB3_HOST1_DP) ; also on sheet 19
USB3_HOST1_SSRXN: M5.185(USB3_HOST1_SSRXN/SATA1_RXN/QSGMII_RXN_M0) ; also on sheet 19
USB3_HOST1_SSRXP: M5.184(USB3_HOST1_SSRXP/SATA1_RXP/QSGMII_RXP_M0) ; also on sheet 19
USB3_HOST1_SSTXN: M5.181(USB3_HOST1_SSTXN/SATA1_TXN/QSGMII_TXN_M0) ; also on sheet 19
USB3_HOST1_SSTXP: M5.180(USB3_HOST1_SSTXP/SATA1_TXP/QSGMII_TXP_M0) ; also on sheet 19
USB3_OTG0_DM: M5.188(USB3_OTG0_DM) ; also on sheet 19
USB3_OTG0_DP: M5.189(USB3_OTG0_DP) ; also on sheet 19
USB3_OTG0_ID: M5.193(USB3_OTG0_ID)
USB3_OTG0_SSRXN: M5.191(USB3_OTG0_SSRXN/SATA0_RXN) ; also on sheet 19
USB3_OTG0_SSRXP: M5.190(USB3_OTG0_SSRXP/SATA0_RXP) ; also on sheet 19
USB3_OTG0_SSTXN: M5.187(USB3_OTG0_SSTXN/SATA0_TXN) ; also on sheet 19
USB3_OTG0_SSTXP: M5.186(USB3_OTG0_SSTXP/SATA0_TXP) ; also on sheet 19
USB3_OTG0_VBUSDET: M5.192(USB3_OTG0_VBUSDET) ; also on sheet 19
USB_OTG_PWREN_H: M5.61(SDMMC0_PWREN/SATA_MP_SWITCH/PCIE20_CLKREQn_M0/GPIO0_A5_d) ; also on sheet 19
VOLN: C87.1 D46.1(I/O2) J17.4 L17.2 TP27.1
VOLP: C88.1 D45.1(I/O2) J17.3 L18.2 TP26.1
VORN: C90.1 D44.1(I/O2) J17.2 L19.2 TP25.1
VORP: C91.1 D43.1(I/O2) J17.1 L20.2 TP24.1
WIFI_REG_ON_H_GPIO3_D4: M5.91(CIF_D6/EBC_SDDO6/SDMMC2_DET_M0/I2S1_SDI2_M1/VOP_BT656_D6_M1/GPIO3_D4_d) ; also on sheet 23
WIFI_WAKE_HOST_H_GPIO3_D5: M5.90(CIF_D7/EBC_SDDO7/SDMMC2_PWREN_M0/I2S1_SDI3_M1/VOP_BT656_D7_M1/GPIO3_D5_d) ; also on sheet 23
N67146313: R46.1 U8.43(OVCJ5) U8.45(OVCJ1)
N67159131: R41.1 U6.3(OCB)
N67228394: C2.1 L1.1 U1.2(LX)
N67228398: C2.2 U1.4(BS)
N67228404: C8.1 R4.2 R6.1 U1.6(FB)
N68117516: D12.1(I/O2) J4.2 R27.2
N68117520: D10.C D11.1(I/O2) J4.1
N68117689: D10.A R25.2 R26.2
N68234263: D38.1(I/O2) J15.3(R) R76.2
N68234265: D40.1(I/O2) J15.2(L) R73.2
N68234885: C80.2 R68.2 R69.1
N68235937: D39.1(I/O2) J15.5(L-COM) R74.2
N68290667: L18.1 U13.1(VOLP)
N68290669: L17.1 U13.3(VOLN)
N68290717: L19.1 U13.14(VORN)
N68290719: L20.1 U13.16(VORP)
N68290721: C86.1 R79.1
N68290723: R79.2 U13.7(INL)
N68290736: C89.1 R80.1
N68290738: R80.2 U13.10(INR)
N68290823: C85.2 U13.8(Bypass)
N68391184: R14.2 U2.1(EN)
N68391237: L2.1 U2.3(SW)
N68391239: C19.1 R12.2 R15.1 U2.5(FB)
N68444772: C488.2 D1.C F1.2 L50.2 R368.1
N68693421: R43.1 U7.3(OCB)
N68696061: R49.1 U9.3(OCB)
N68696295: R53.1 U10.3(OCB)
N68706836: R57.1 U11.3(OCB)
N68707388: R59.1 U12.3(OCB)
N68764417: C16.1 L3.1 U39.2(LX)
N68764421: C16.2 U39.4(BS)
N68764430: C24.1 R13.2 R17.1 U39.6(FB)
N68784083: C83.2 R75.2 R78.1
N68821934: LED1.1 R8.2
N68821936: LED1.3 R9.2
N69153757: C12.2 R3.2 R5.1 U39.5(EN)
N69164567: R16.2 U1.5(EN)
N69167857: R381.1 U40.3(OCB)

Not connected (* = marked no-connect by the designer): J2 1* 5 6; J15 6(R-COM)*; M1 1*; M2 1*; M3 1*; M4 1*; M5 205(SNSN) 206(SNSP) 207(BATDIV); U8 1(DRV) 2(TESTJ) 3(LED1) 4(LED2) 5(LED3) 7(LED4) 44(PWRJ) 46(LED7) 47(LED6) 48(LED5)

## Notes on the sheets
sheet 1
- Revision History
- Version
- Date
- Author
- Change Note
- Approved
- V1A
- 2020.08.20
- First edition
sheet 2
- RK3568 Ref Block Diagram(Default configuration)
- Debug
  UART2
- RJ-45
- RJ-45
- UART2
- WIFI/BT
- Giga PHY
- Giga PHY
- DOG
- AP6255
- RTL8211F-CG
- RTL8211F-CG
- KEY
- HR7P153
  P4SA_BM
- GPIO×3
- SPI0
- FLASH
  1MB
- SD
- BUZZZER
- GPIO×1
- PMUIO1
  PMUIO2
- HDMI2.0
  TX
- MIPI
  DSI
  LVDS
  TX0
- MIPI
  DSI
  TX1
- VCCIO7
- VCCIO4
- RGMII0
- GPIO×2
- LED STATUS × 2
- GPIO×8
- RS485-LED-STATUS × 8
- VCCIO6
- RGMII1_M1
- VCCIO6
- LED BOARD CONNECTOR
- PCIE3.0
- MIPI
  CSI
  RX
- PH × 4
- INDUSTIO
- USB2.0
  HOST2
- MULTI_
  PHY2
- PCIE2.0
  SATA2
  QSGMII_M1
- HOST2_LS/FS/HS
- USB2
  HOST2
  HOST3
- PH × 4
- MULTI_
  PHY1
- USB3_HOST1
  SATA1
  QSGMII_M0
- HOST3_LS/FS/HS
- USB2.0
  HOST3
- USB3_OTG0_SS
- MULTI_
  PHY0
- USB3_OTG0
  SATA0
- SOM3568-CORE
- VCCIO3
- SDMMC0 x 4bit
- Quad A55
- USB2
  OTG0
  HOST1
- Micro
  SD Card
- USB2_OTG0_LS/FS/HS
- GPIO×8
- Micro
  SD Card
- USB3.0
  OTG0
  TYPE-C
- SS
- VCCIO5
- GPIO×4
- eDP
- Phoenix × 12
- Contact × 8
- Realy × 4
- Phoenix × 8
- DC/DC
- Power for SOM3568
- MAIN
  POWER
- 5.0V
- RK809-5
- VCCIO1
- SARADC
- 12V
  Adapter
- Phoenix × 12
- I2C3
- SARADC_IN0
- SP485E
  EN-L/TR
- SP485E
  EN-L/TR
- SP485E
  EN-L/TR
- SP485E
  EN-L/TR
- RTC
  HYM8563
- UART3
- UART4
- UART5
- RECOVERY-KEY
- UART7
sheet 4
- DC IN
- VDD_5V
- Note:Please use a 12V DC.
- 5V@5.5A
- VDC
- LED
- VCC5V0_SYS
- VDD_3V3
- 5V@5.5A
sheet 5
- HDMI2.0_TX
- MIPI_RX
- MicroSD Card
- MIPI_DSI_TX0
- PCIE2.0
- Debug UART2
- MIPI_DSI_TX1
- RK809-5
- USB3.0
- eDP_TX
- ADC
- USB2.0
- VCCIO4_1.8V_3.3V
- Default 1.8V
- VCCIO5_3.3V
- Default 3.3V
- Default 1.8V
- PMUIO1/2_3.3V
- Default 3.3V
- VCCIO6_1.8V_3.3V
- VCCIO1_3.3V
- Default 3.3V
- VCCIO7_3.3V
- Default 3.3V
sheet 6
- MicroSD Card
- Debug UART2
sheet 7
- HUB_FE2.1
- 内部偏值参考电阻
